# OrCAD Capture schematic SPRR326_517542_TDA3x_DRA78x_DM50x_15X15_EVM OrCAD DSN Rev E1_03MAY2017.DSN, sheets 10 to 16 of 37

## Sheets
10 SH16 - USB FTDI UART: size C; rev: A
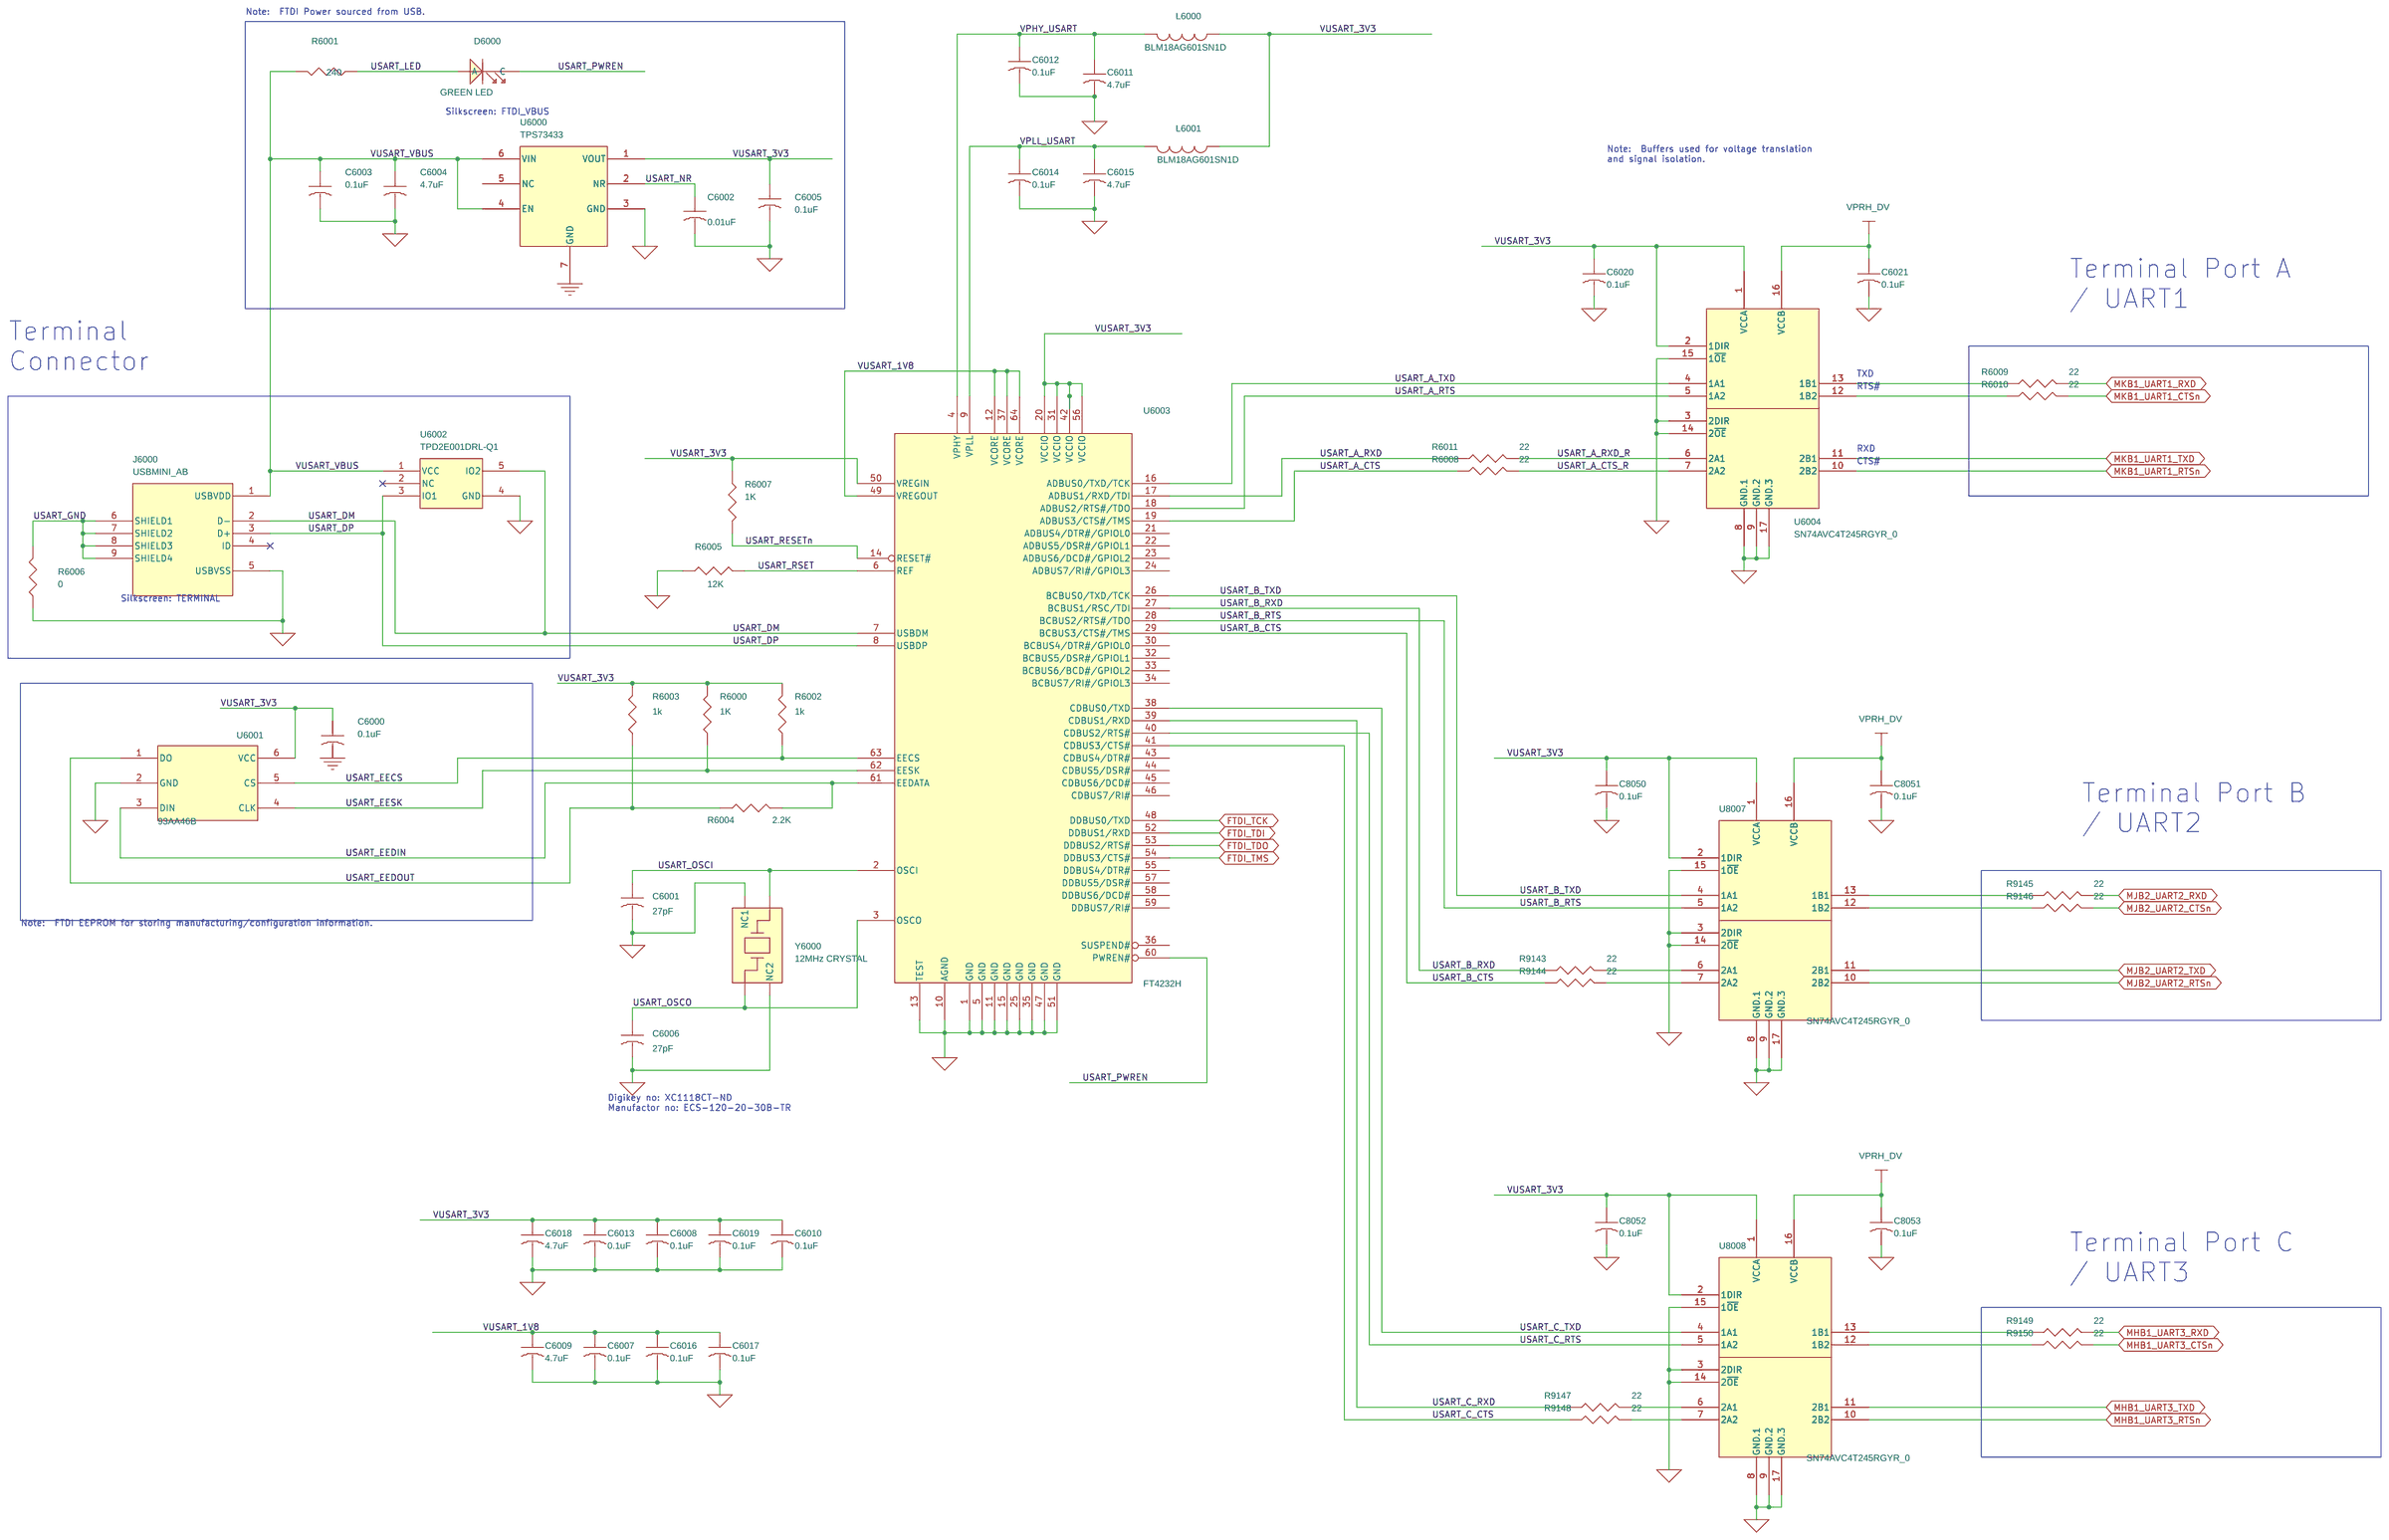
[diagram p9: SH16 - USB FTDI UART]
11 SH18 - ETHERNET: size C; rev: A
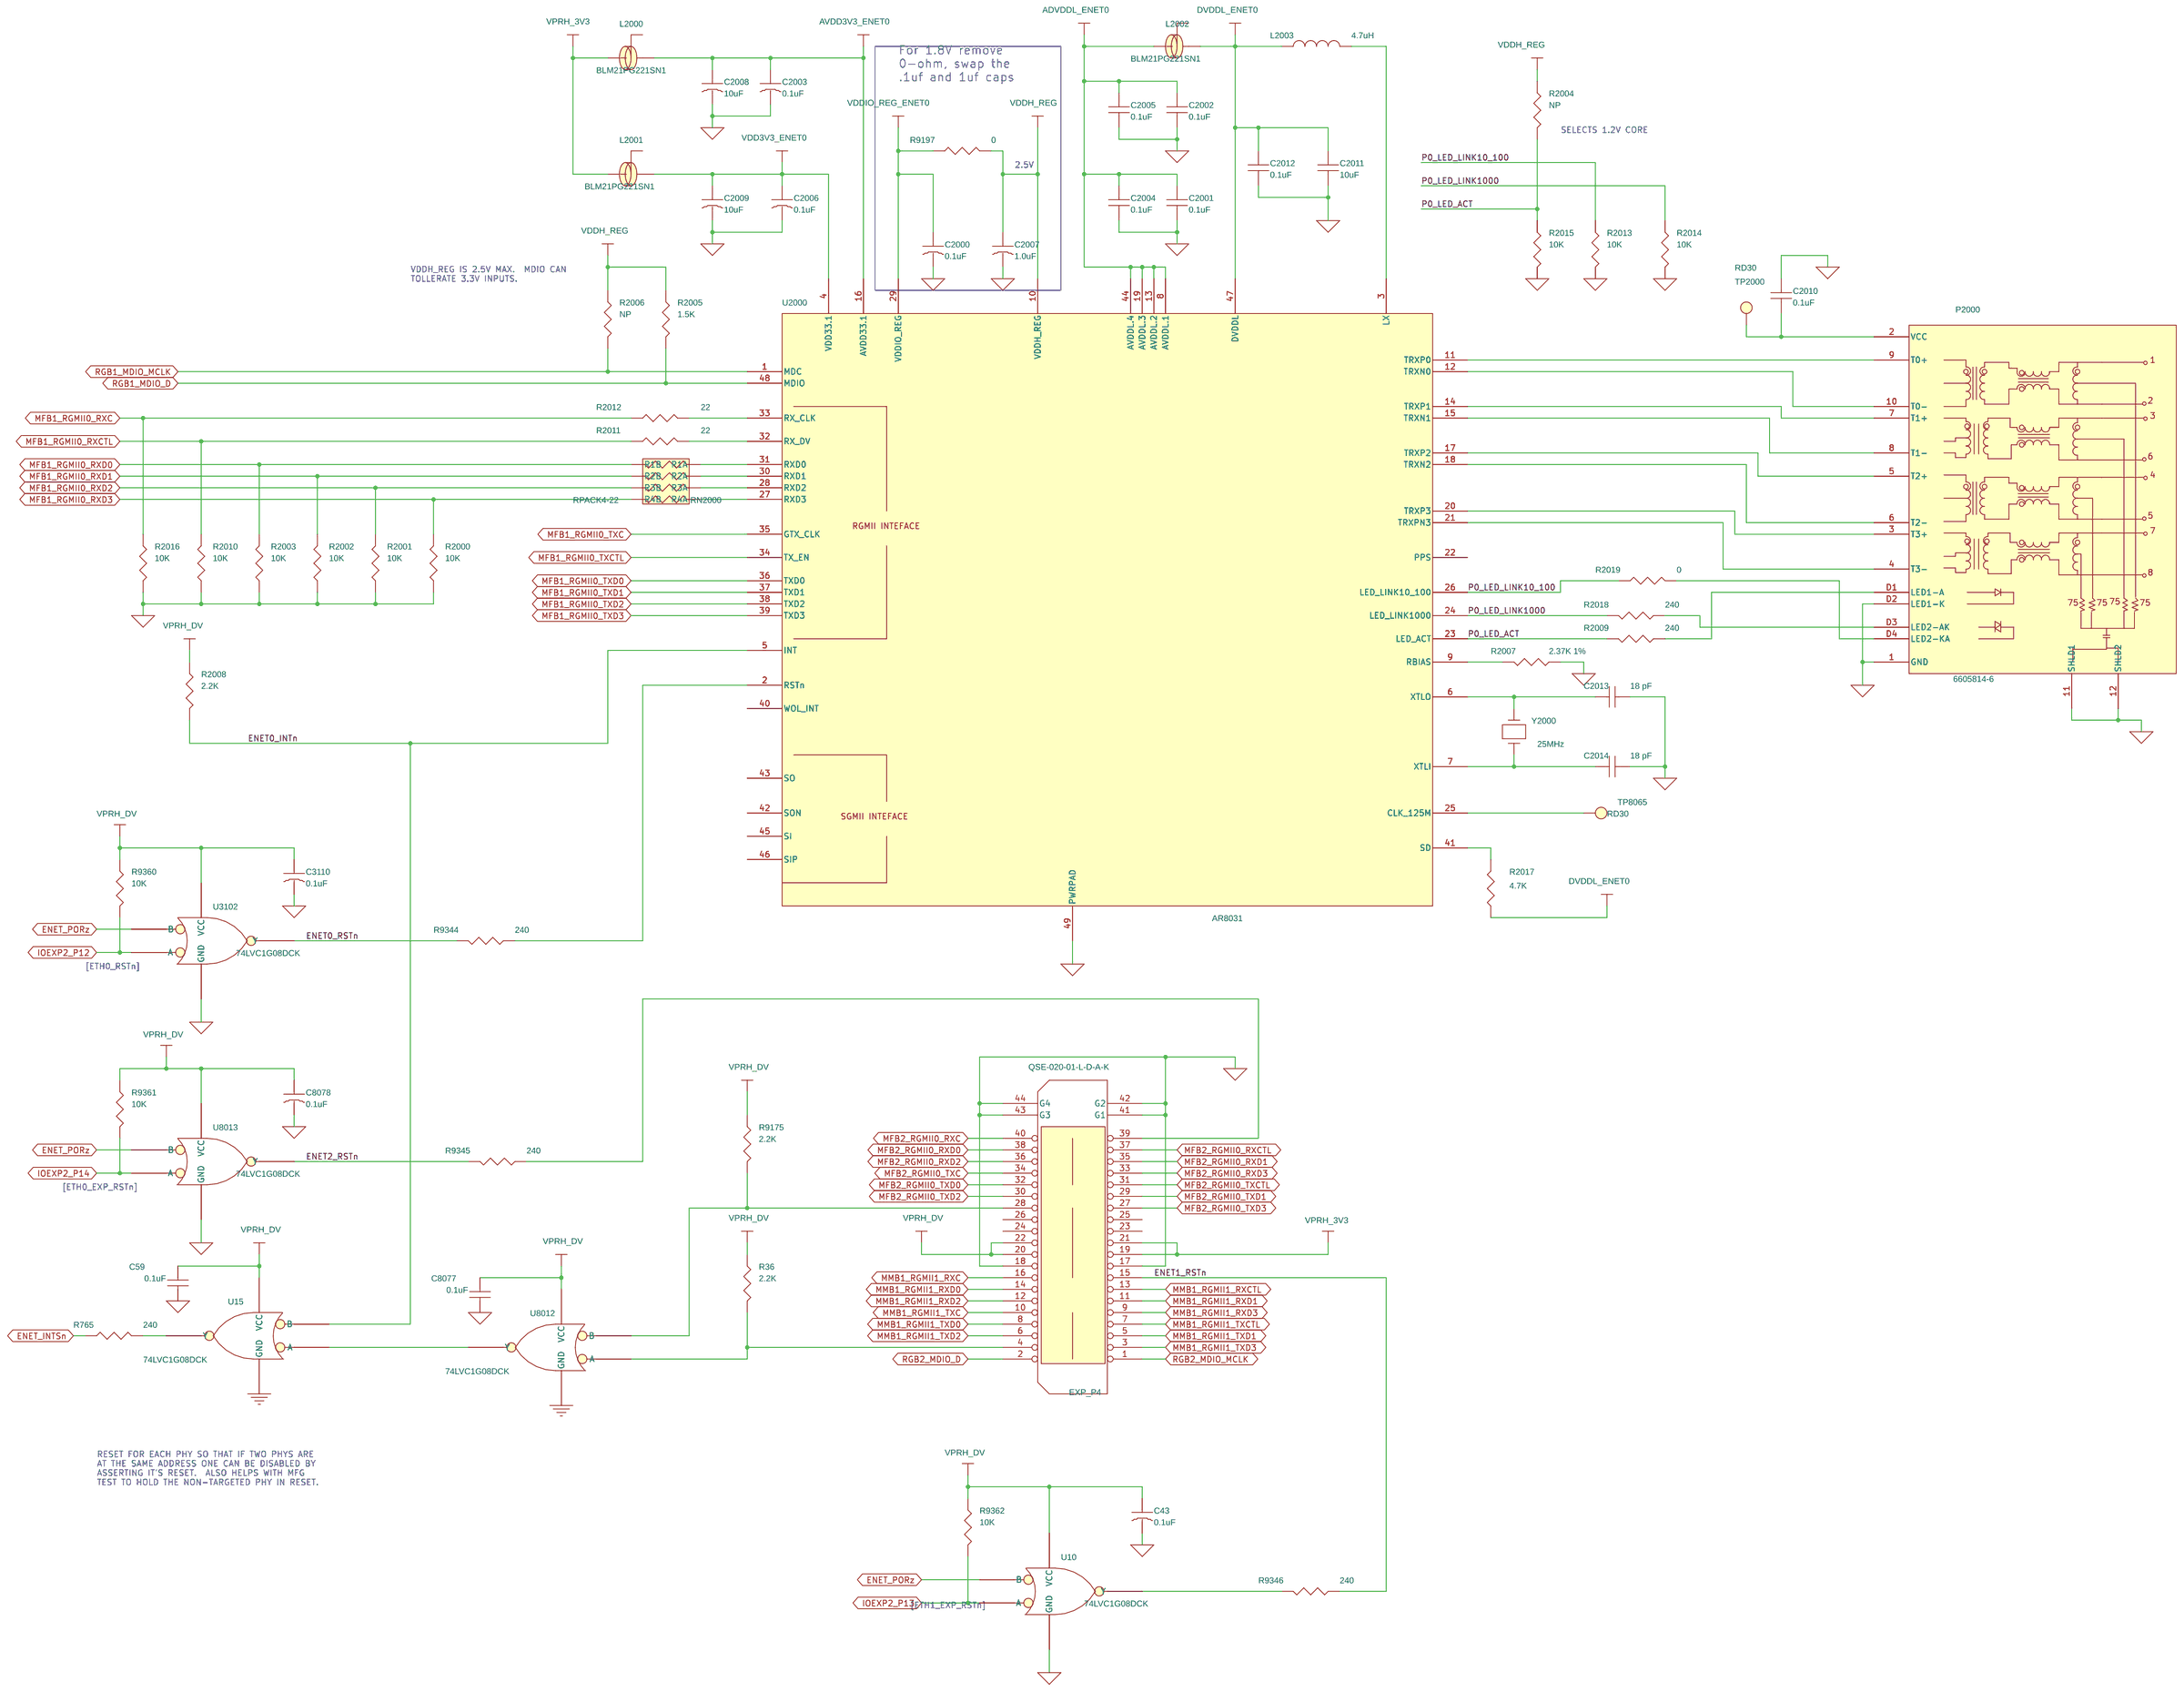
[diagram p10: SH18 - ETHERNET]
12 SH19 - POWER TPS443351DAP: size C; rev: D
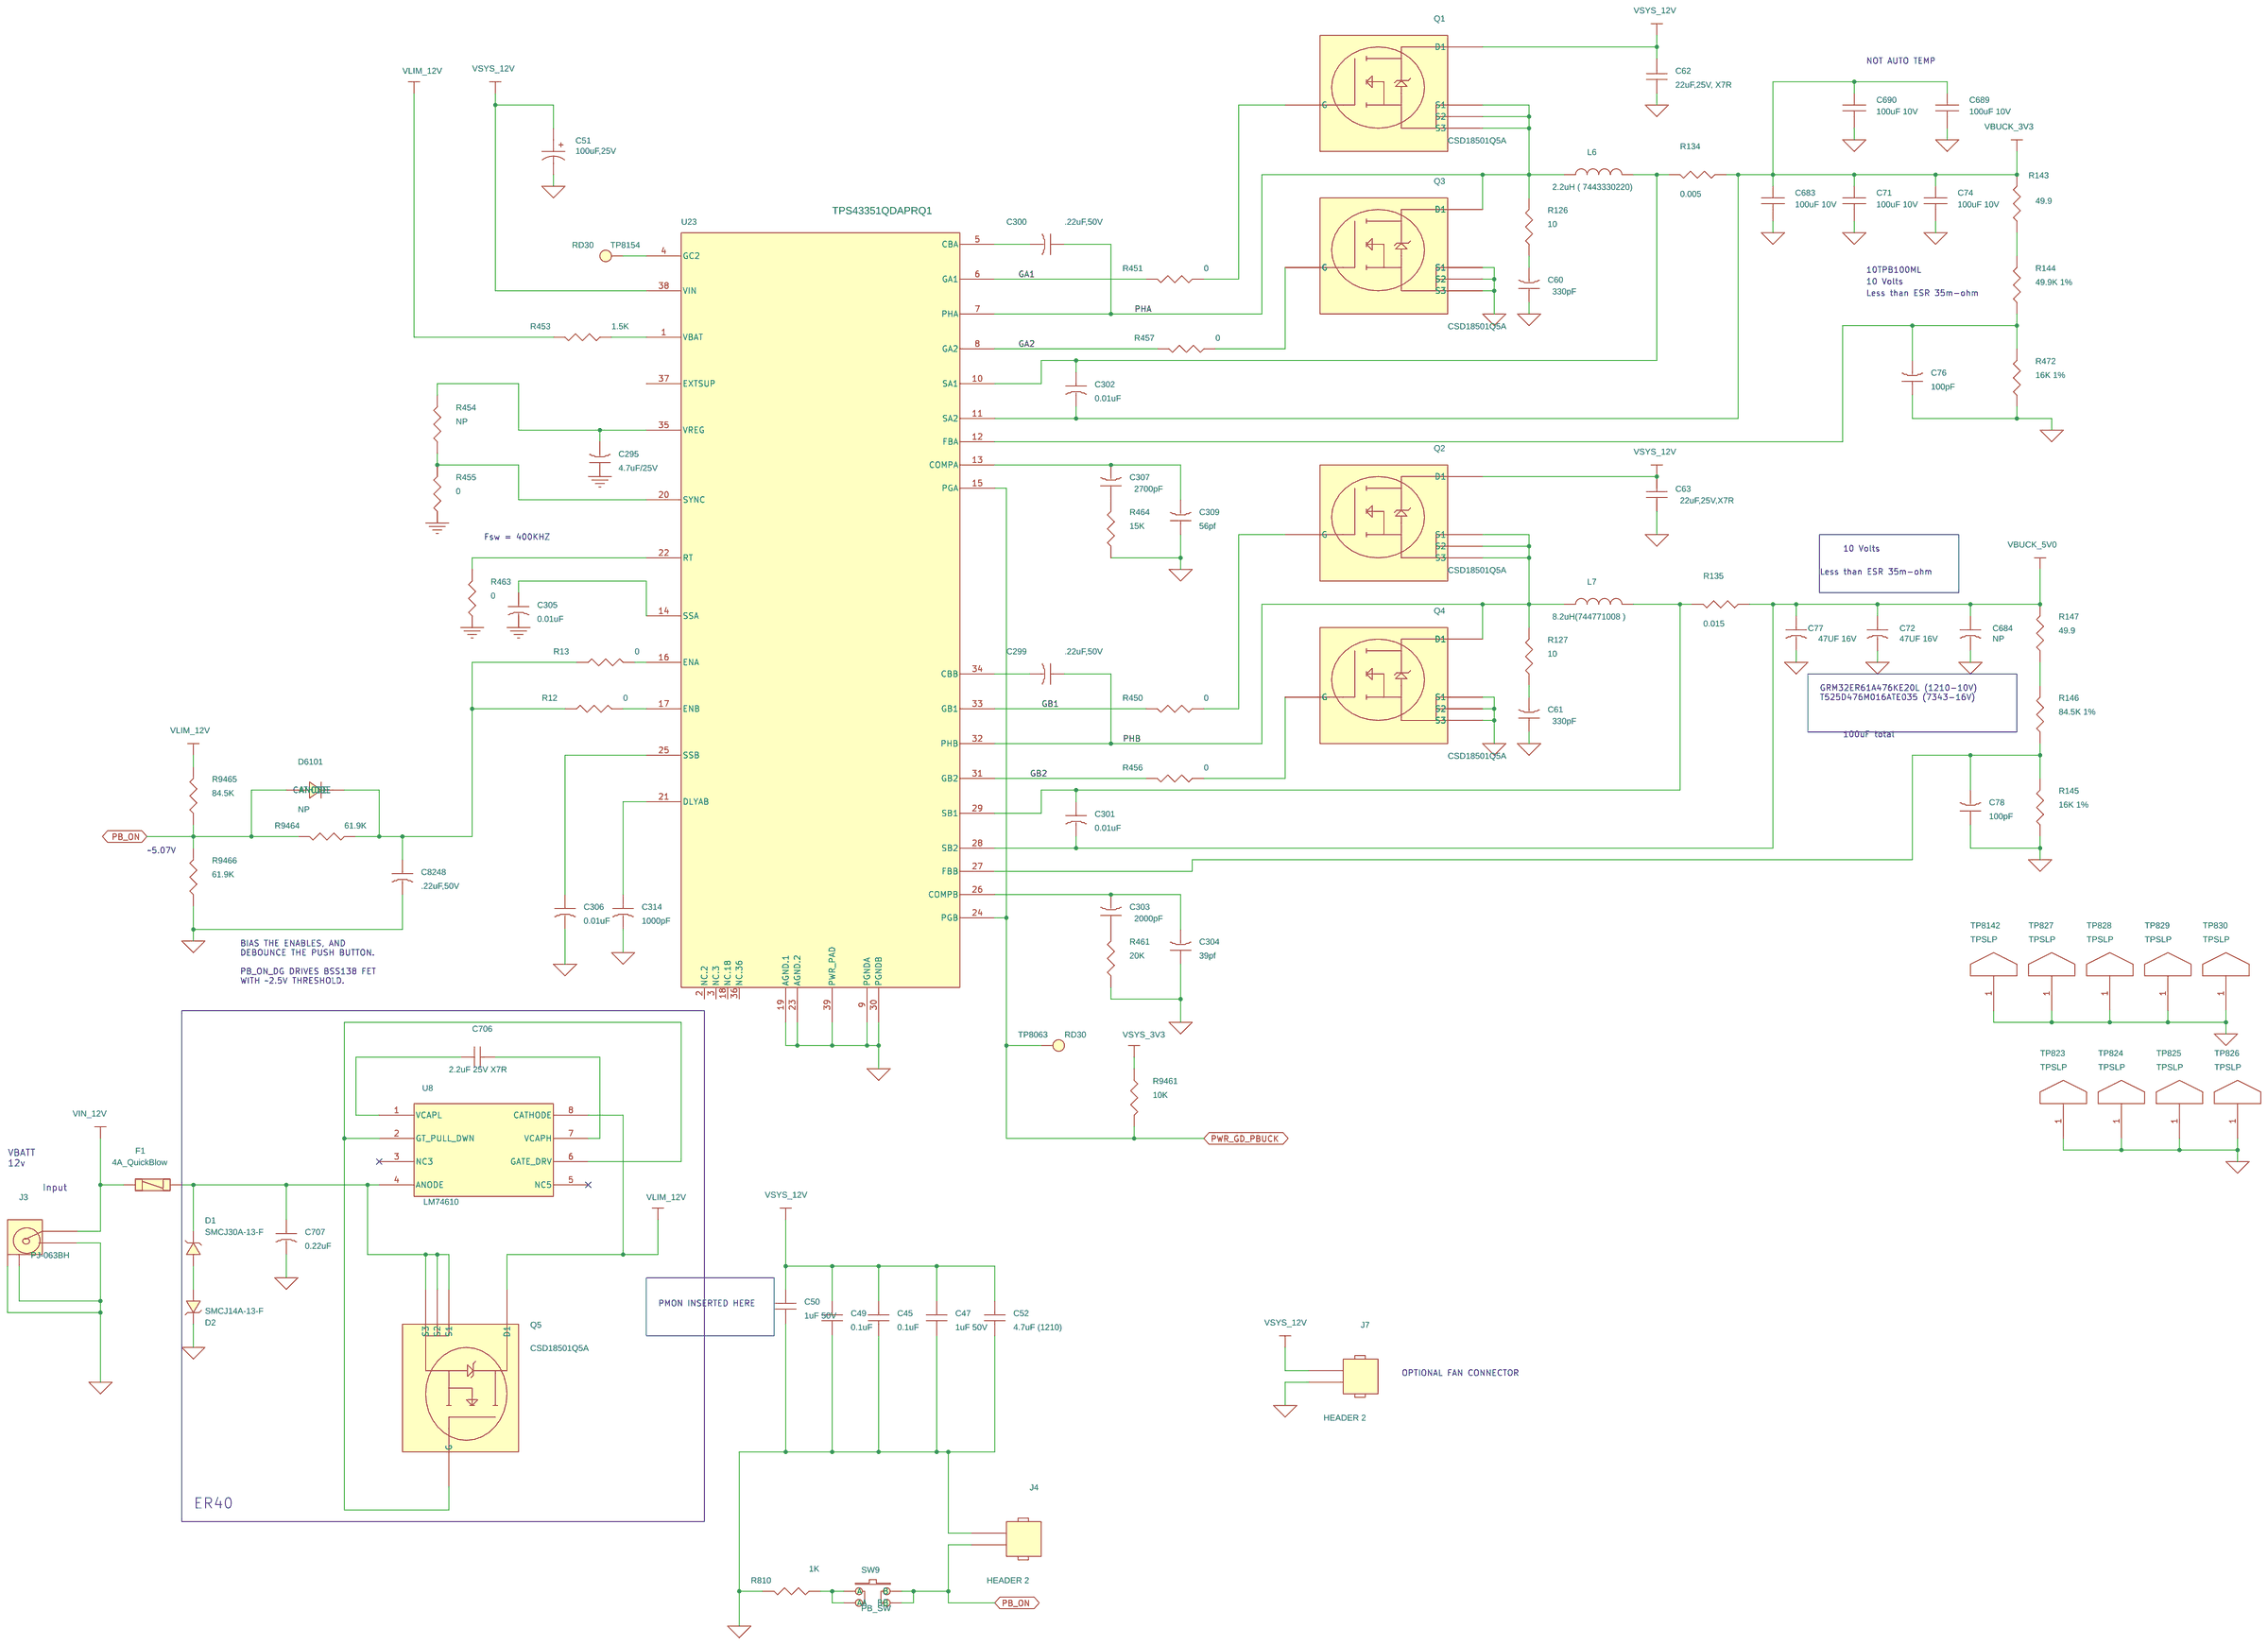
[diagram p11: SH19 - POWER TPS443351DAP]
13 SH20 - POWER PMIC: size C; rev: D
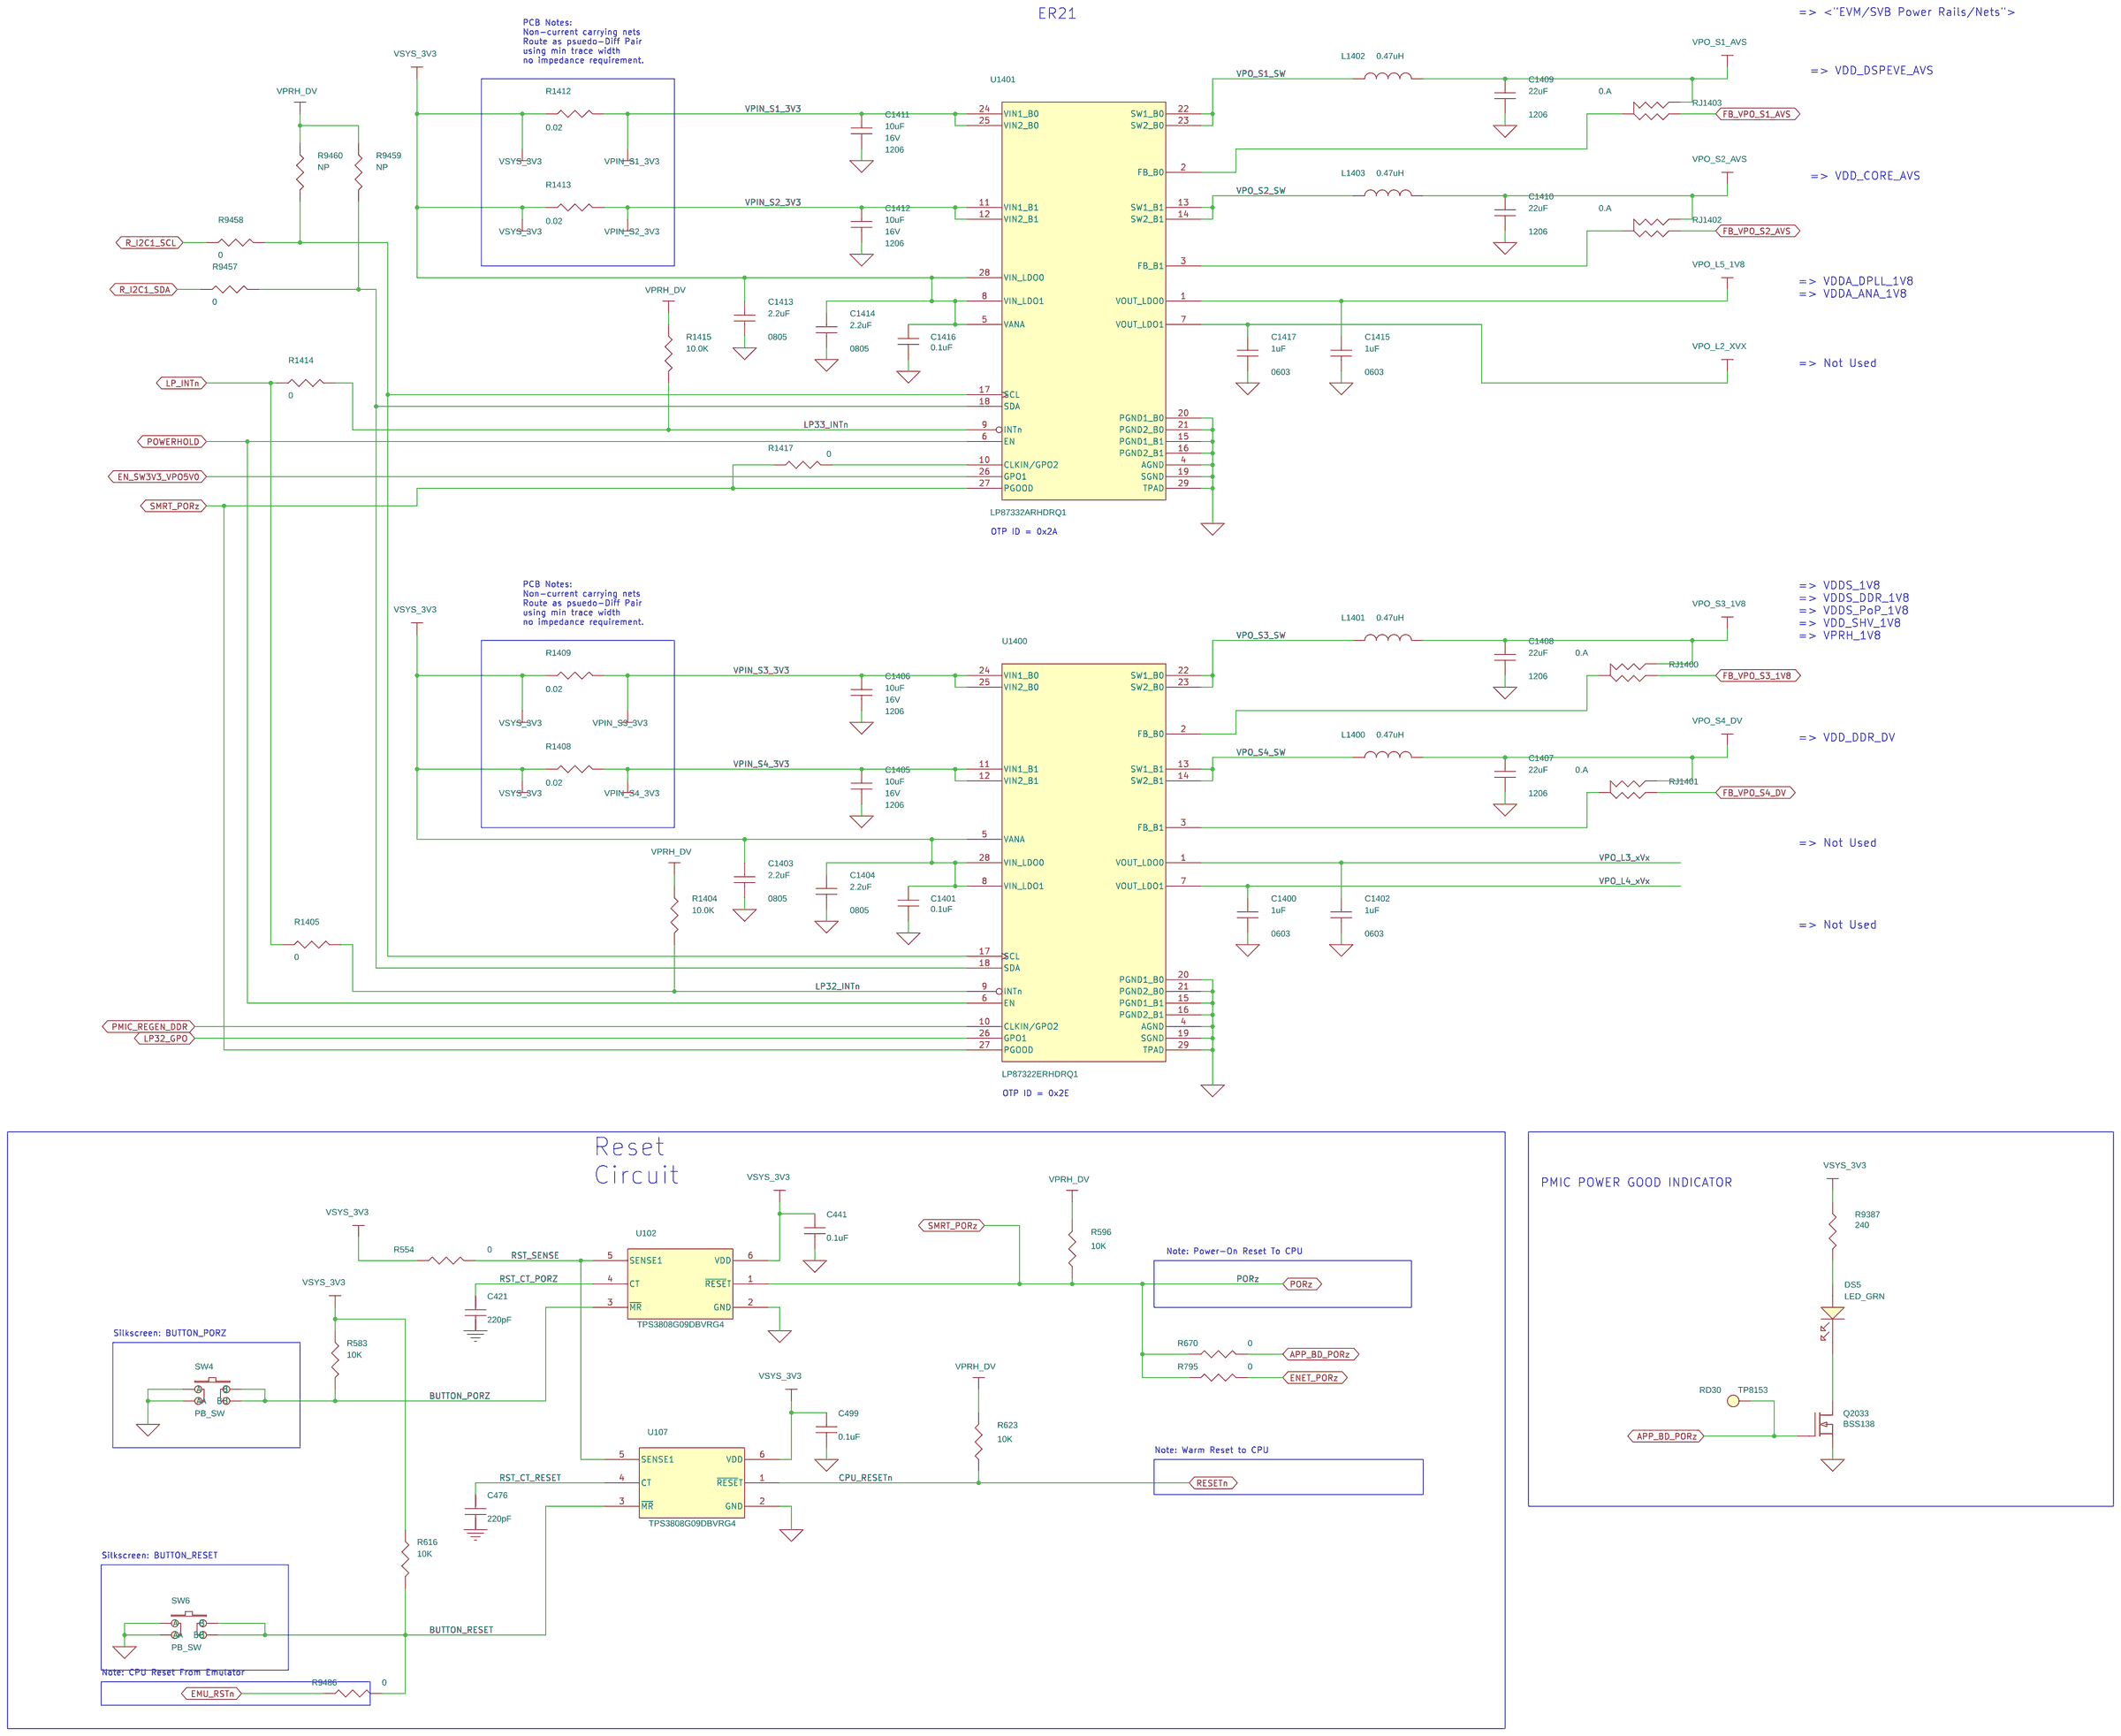
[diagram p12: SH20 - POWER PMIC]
14 SH21 - POWER MISC SWITCHES: size C; rev: E
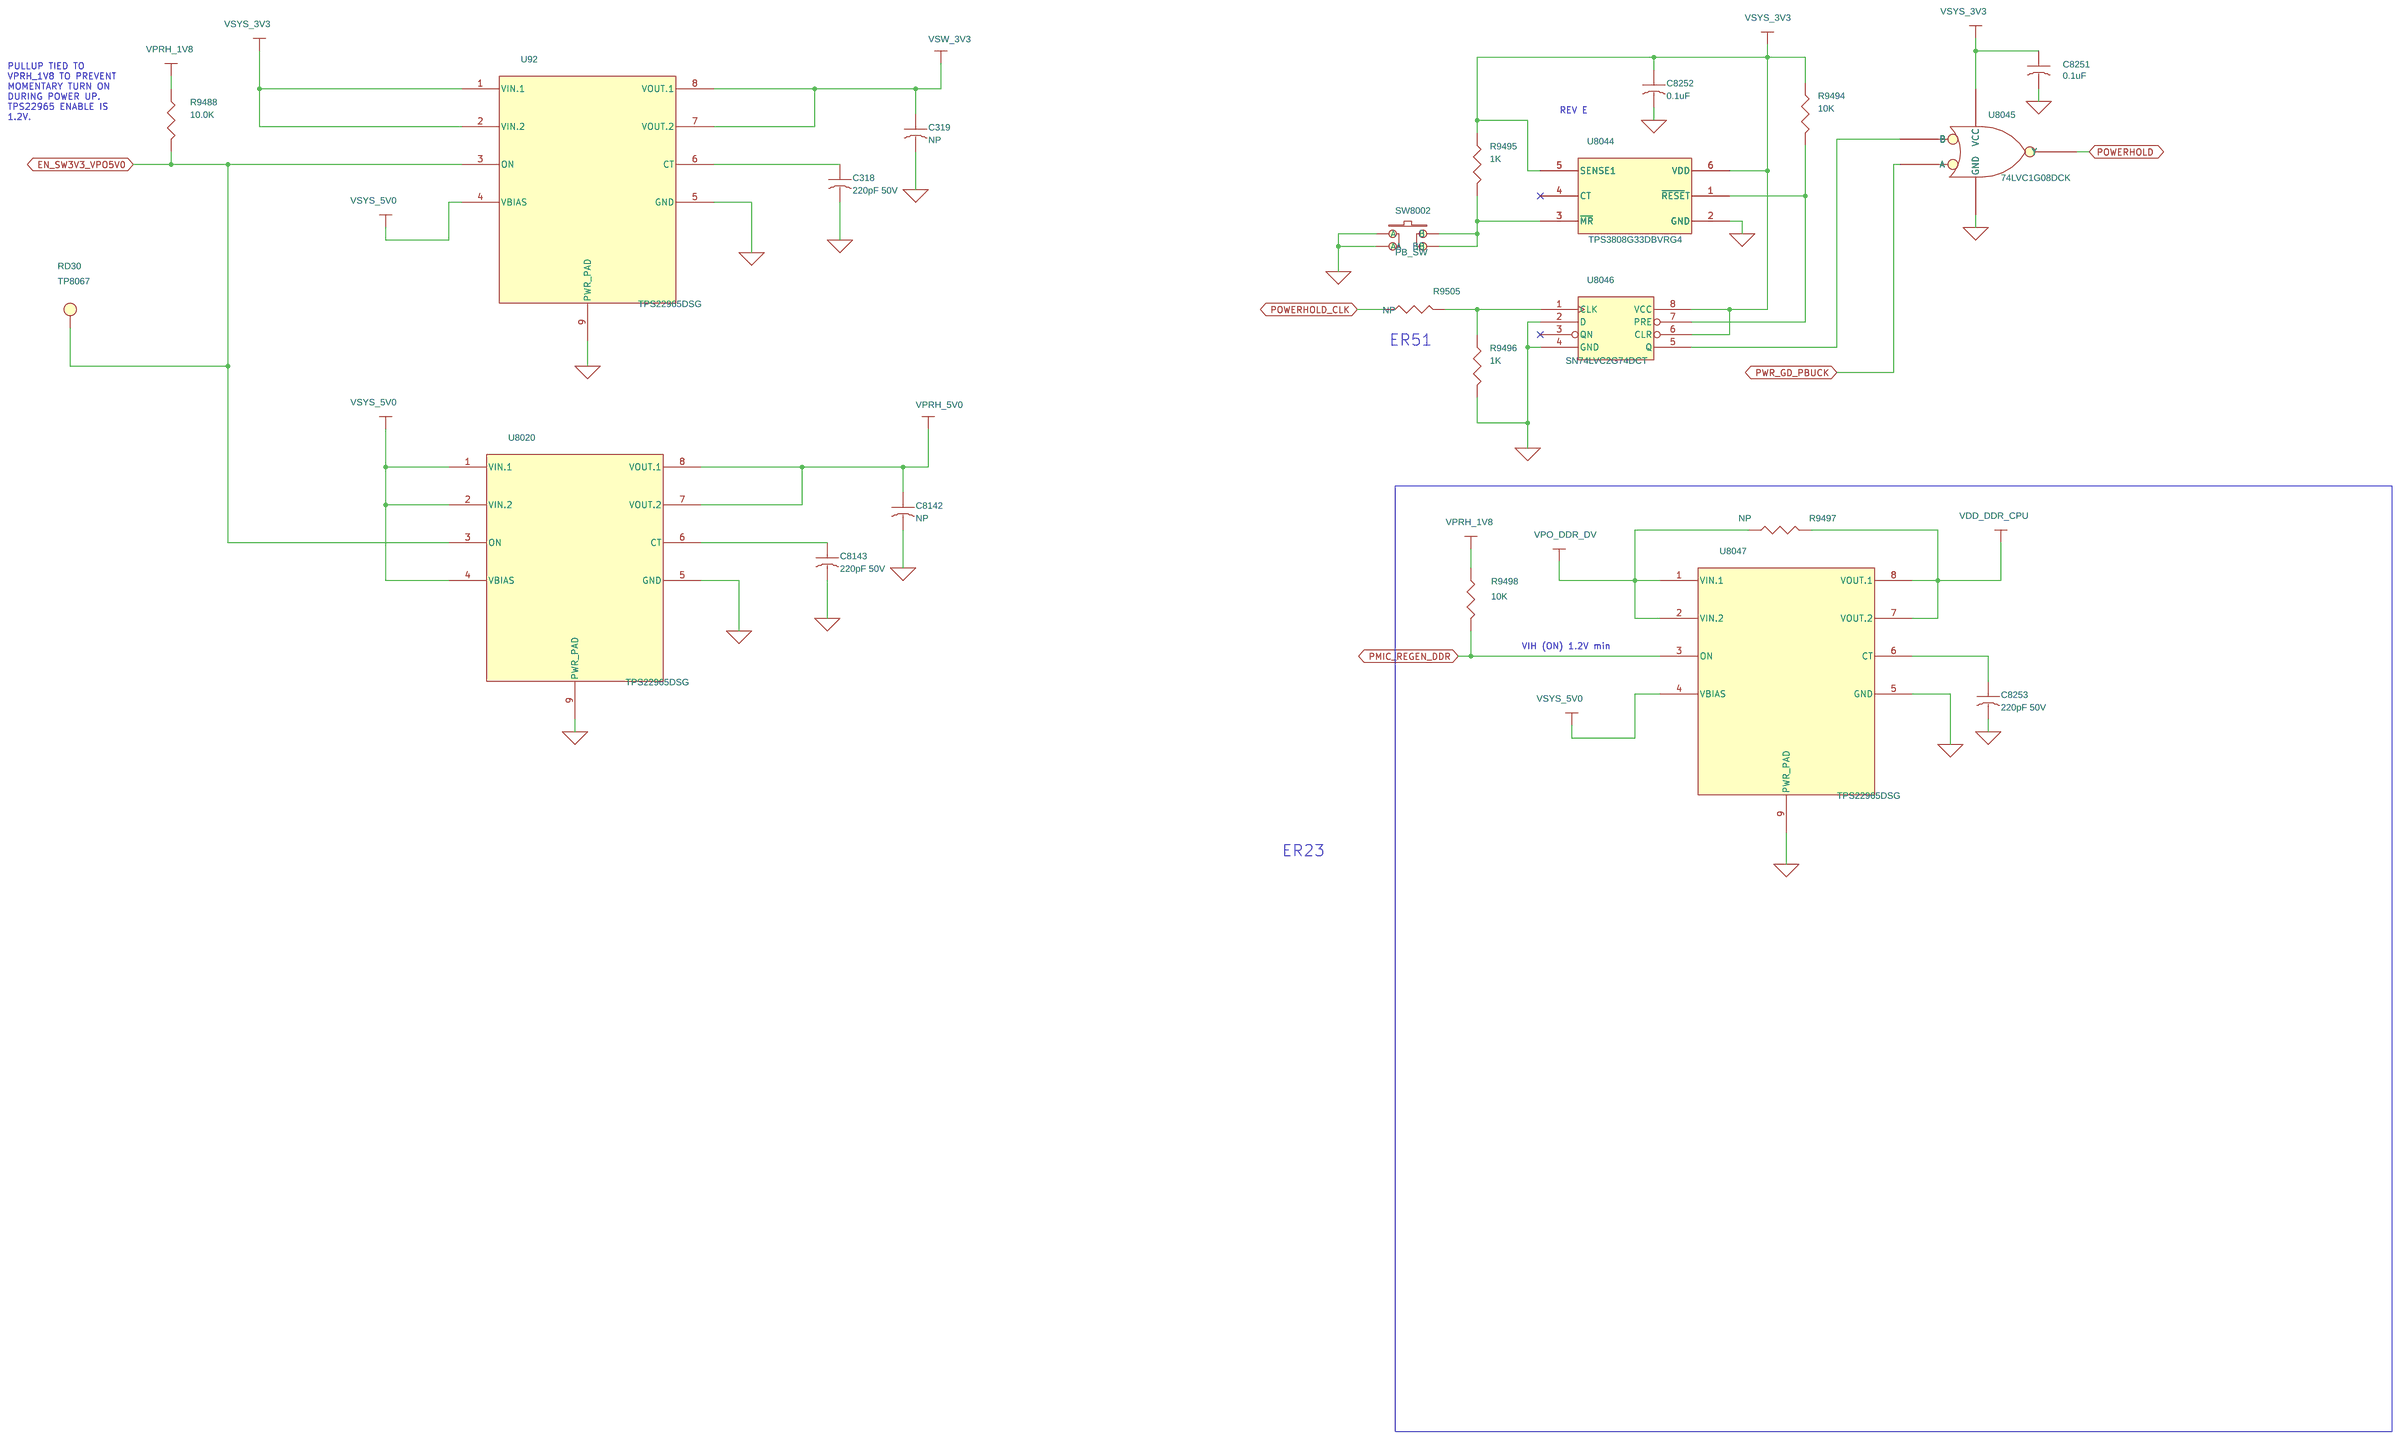
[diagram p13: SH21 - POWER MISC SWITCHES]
15 SH22 - POWER MONITORS: size C; rev: B
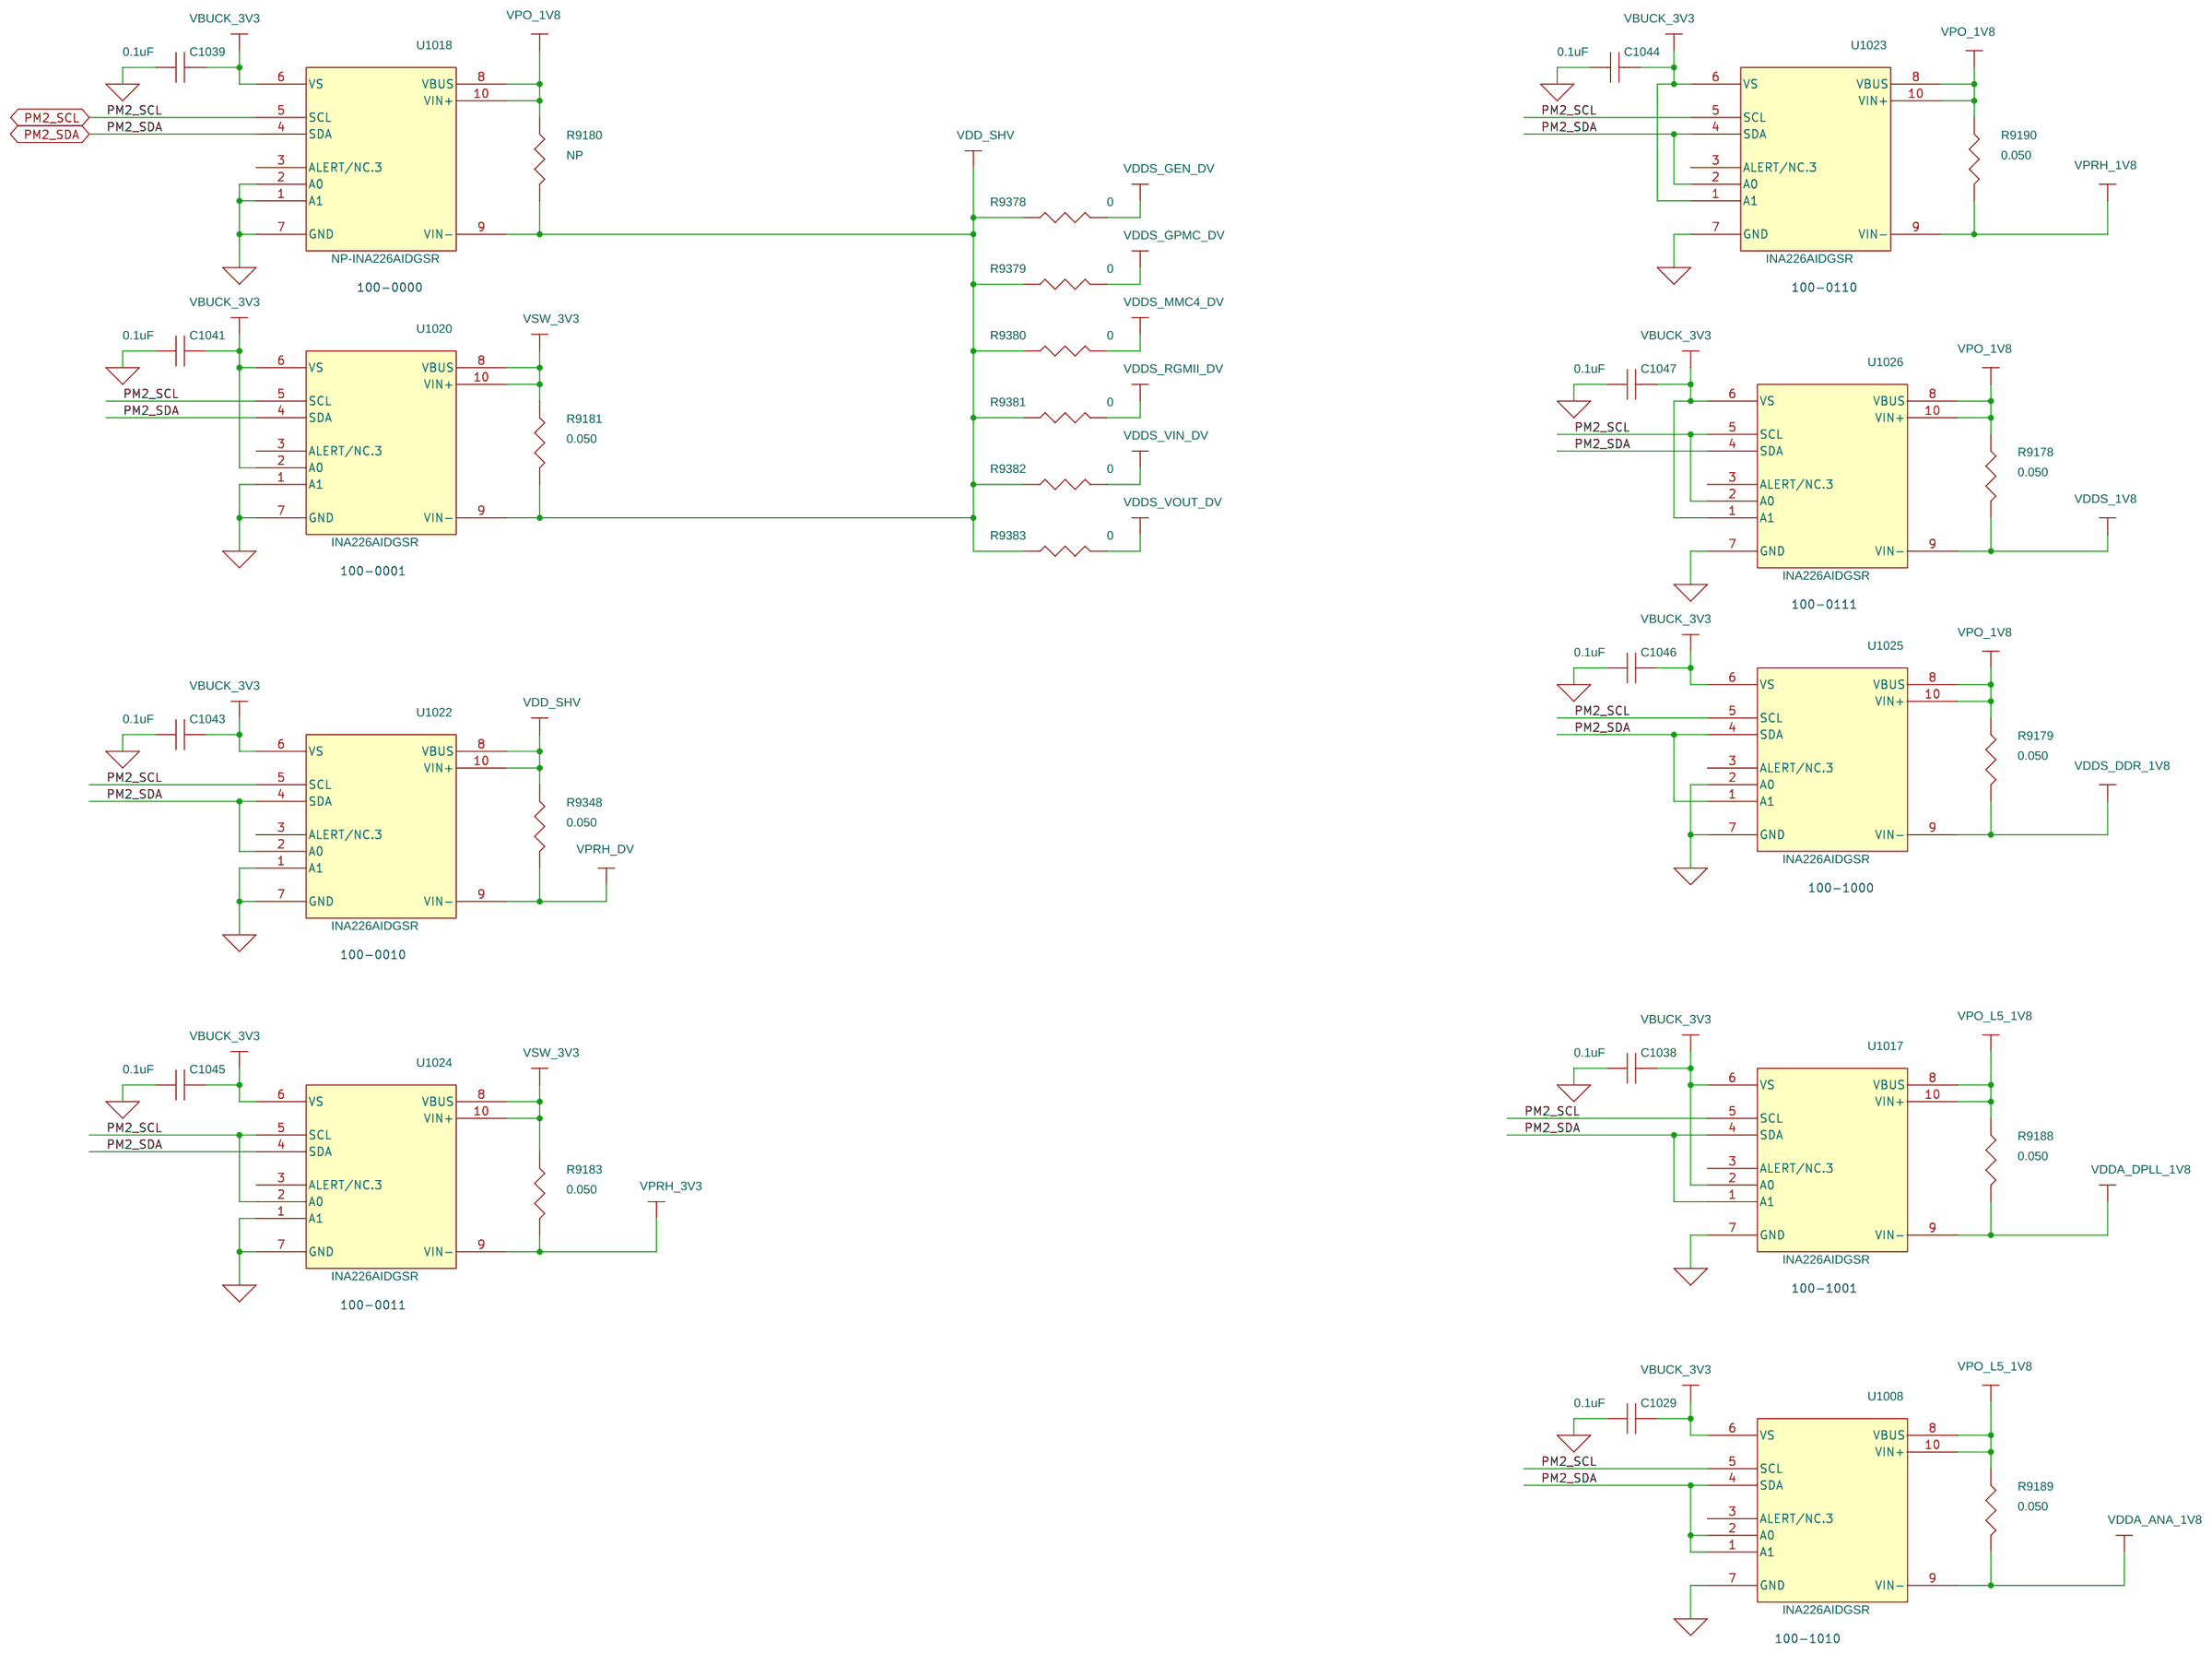
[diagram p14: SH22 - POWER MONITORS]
16 SH24 - VOUT LCD CONNECTOR: size C; rev: A
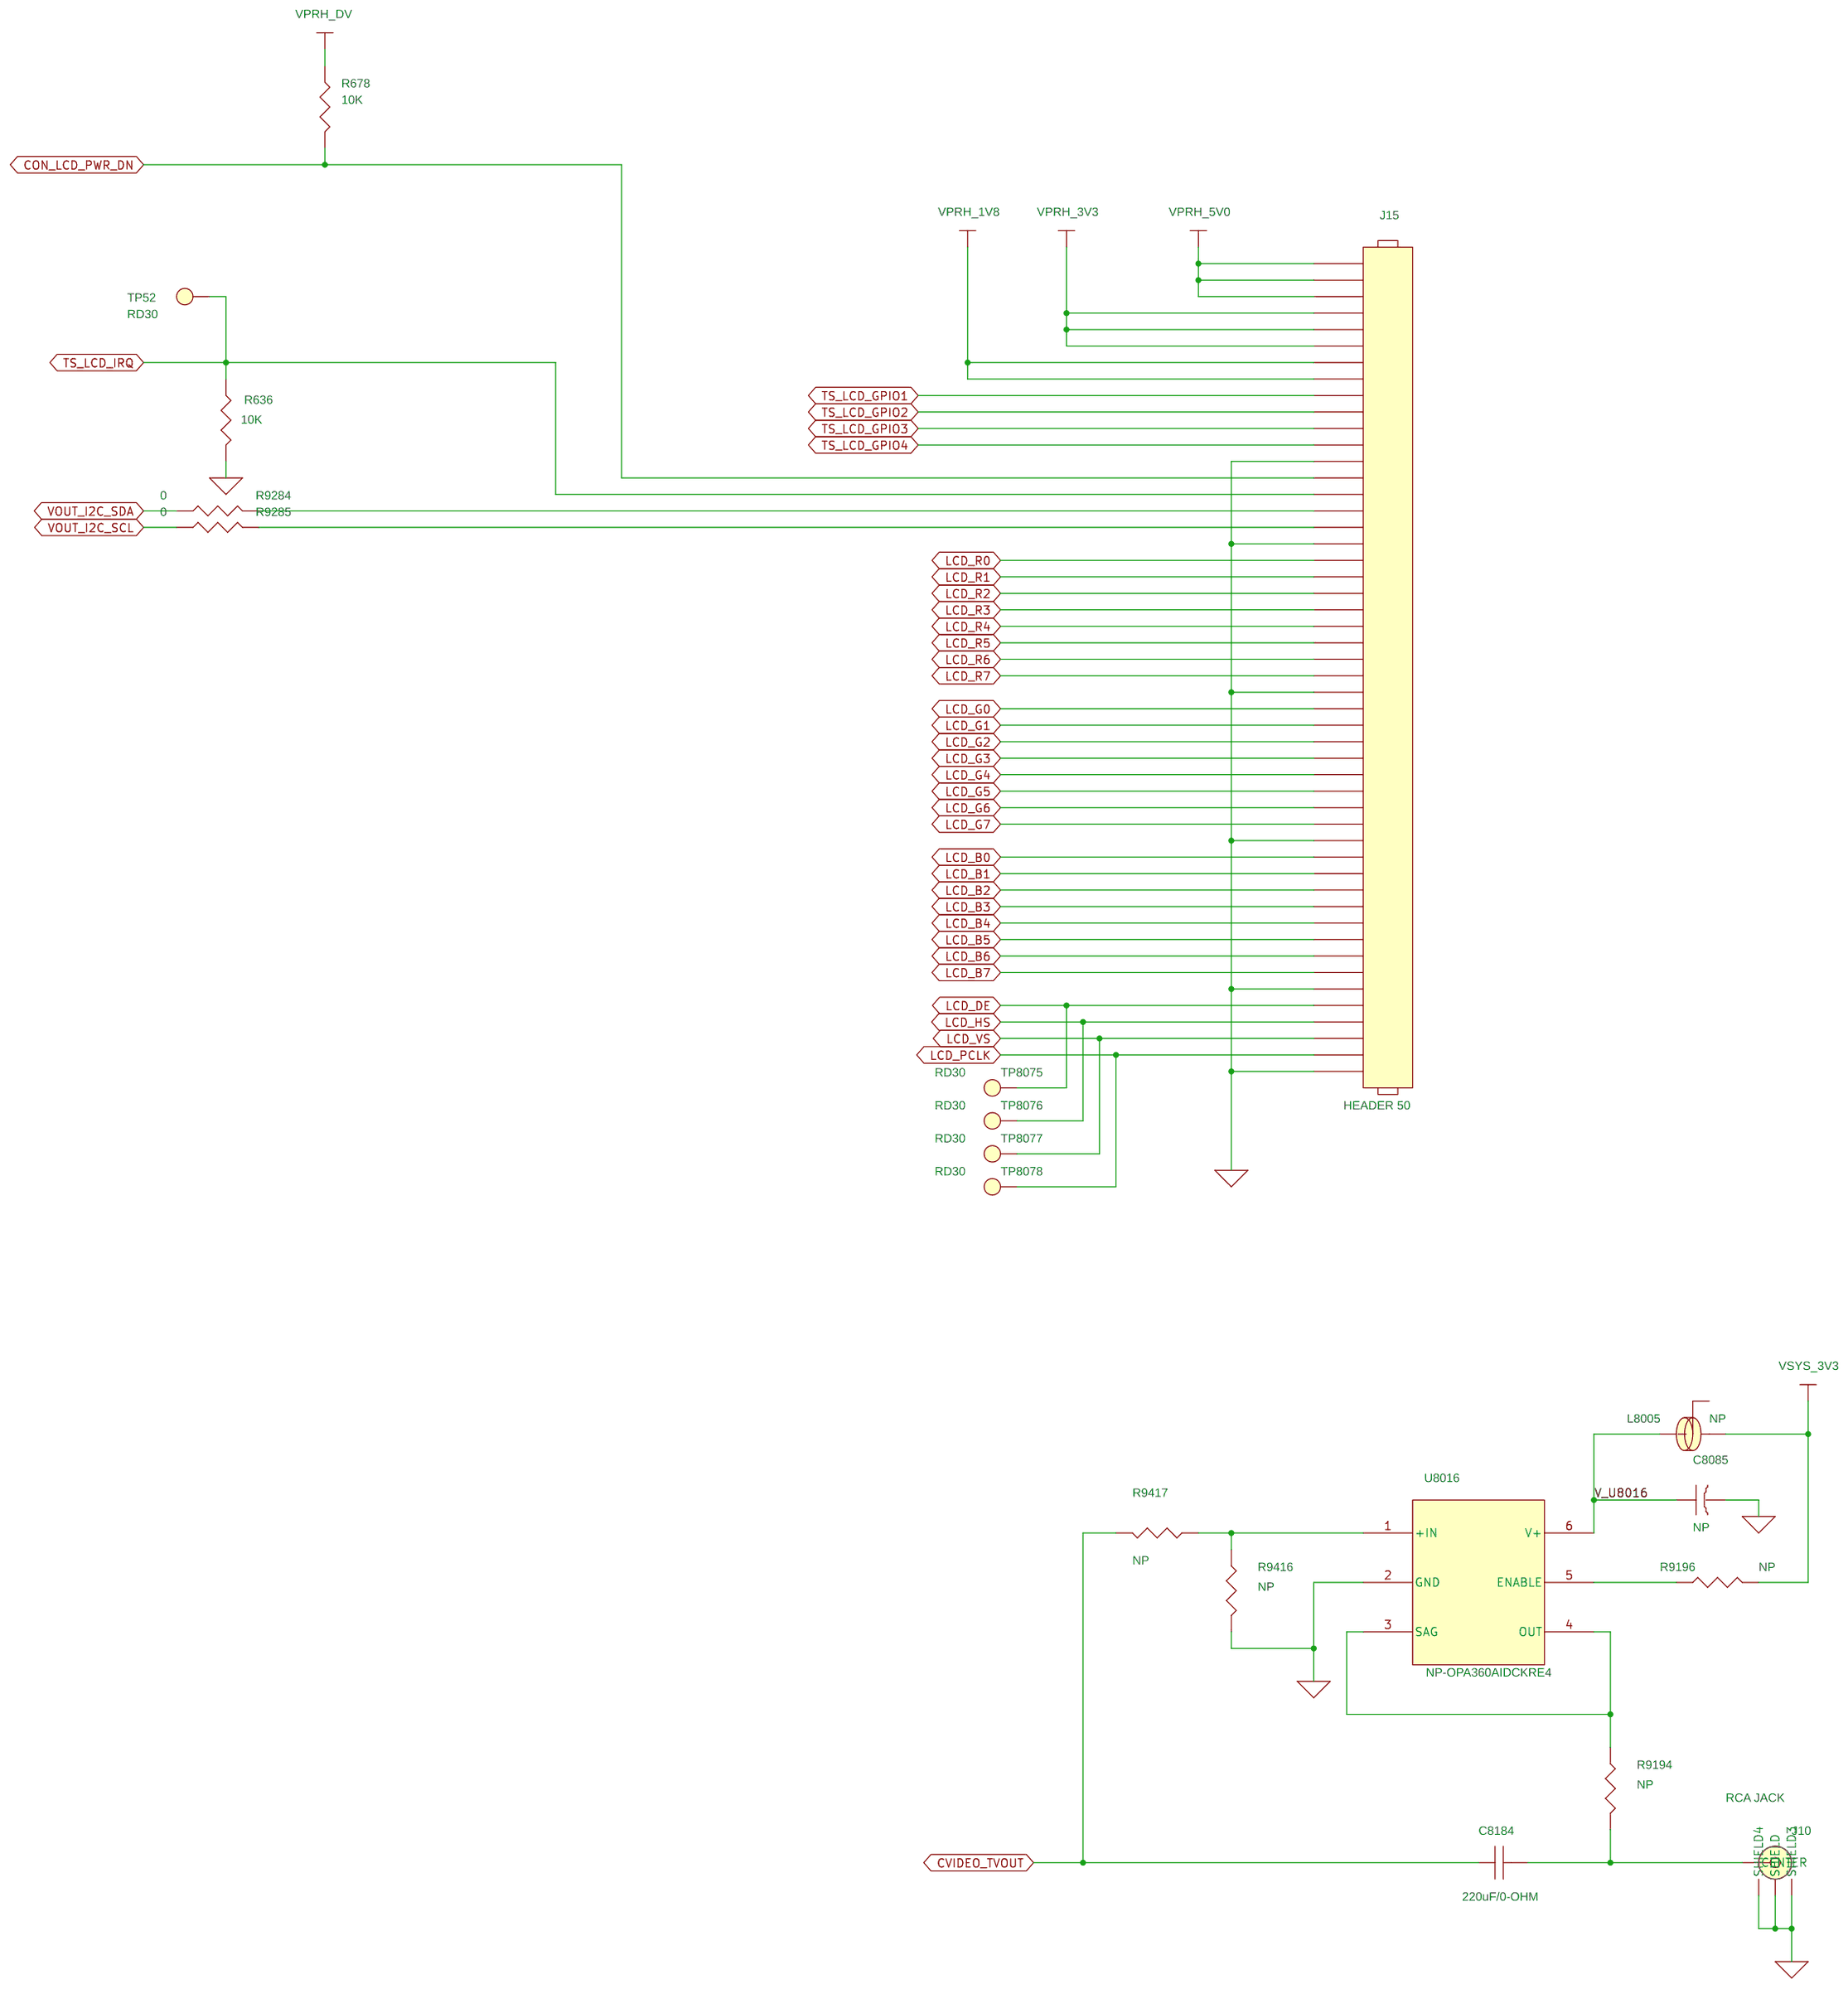
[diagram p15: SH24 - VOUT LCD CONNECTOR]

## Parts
sheet SH16 - USB FTDI UART
C6000  0.1uF  [c402-25]
C6001  27pF  [c402-25]
C6002  0.01uF  [c402-25]
C6003  0.1uF  [c402-25]
C6004  4.7uF  [C805-35X60]
C6005  0.1uF  [c402-25]
C6006  27pF  [c402-25]
C6007  0.1uF  [c402-25]
C6008  0.1uF  [c402-25]
C6009  4.7uF  [C805-35X60]
C6010  0.1uF  [c402-25]
C6011  4.7uF  [C805-35X60]
C6012  0.1uF  [c402-25]
C6013  0.1uF  [c402-25]
C6014  0.1uF  [c402-25]
C6015  4.7uF  [C805-35X60]
C6016  0.1uF  [c402-25]
C6017  0.1uF  [c402-25]
C6018  4.7uF  [C805-35X60]
C6019  0.1uF  [c402-25]
C6020  0.1uF  [c402-25]
C6021  0.1uF  [c402-25]
C8050  0.1uF  [c402-25]
C8051  0.1uF  [c402-25]
C8052  0.1uF  [c402-25]
C8053  0.1uF  [c402-25]
D6000  GREEN LED  [led603-35x45-rev]
J6000  USBMINI_AB  [SAMTEC-MUSB]
L6000  BLM18AG601SN1D  [l603-35x45]
L6001  BLM18AG601SN1D  [l603-35x45]
R6000  1K  [r402-25]
R6001  240  [r402-25]
R6002  1k  [r402-25]
R6003  1k  [r402-25]
R6004  2.2K  [r402-25]
R6005  12K  [r402-25]
R6006  0  [r402-25]
R6007  1K  [r402-25]
R6008  22  [r402-25]
R6009  22  [r402-25]
R6010  22  [r402-25]
R6011  22  [r402-25]
R9143  22  [r402-25]
R9144  22  [r402-25]
R9145  22  [r402-25]
R9146  22  [r402-25]
R9147  22  [r402-25]
R9148  22  [r402-25]
R9149  22  [r402-25]
R9150  22  [r402-25]
U6000  TPS73433  [drv6-12x30]
U6001  93AA46B  [DBV6-27X39-6]
U6002  TPD2E001DRL-Q1  [drl5-12x40]
U6003  FT4232H  [PQFP64PM]
U6004  SN74AVC4T245RGYR_0  [rgy16-12x34]
U8007  SN74AVC4T245RGYR_0  [rgy16-12x34]
U8008  SN74AVC4T245RGYR_0  [rgy16-12x34]
Y6000  12MHz CRYSTAL  [xtal4-63x50-ecx53b]
sheet SH18 - ETHERNET
C43  0.1uF  [c402-25]
C59  0.1uF  [c402-25]
C2000  0.1uF  [c603-35x45]
C2001  0.1uF  [c402-25]
C2002  0.1uF  [c402-25]
C2003  0.1uF  [c402-25]
C2004  0.1uF  [c402-25]
C2005  0.1uF  [c402-25]
C2006  0.1uF  [c402-25]
C2007  1.0uF  [c603-35x45]
C2008  10uF  [c805-35x60]
C2009  10uF  [c805-35x60]
C2010  0.1uF  [c402-25]
C2011  10uF  [c805-35x60]
C2012  0.1uF  [c402-25]
C2013  18 pF  [c402-25]
C2014  18 pF  [c402-25]
C3110  0.1uF  [c402-25]
C8077  0.1uF  [c402-25]
C8078  0.1uF  [c402-25]
EXP_P4  QSE-020-01-L-D-A-K  [QSE_020]
L2000  BLM21PG221SN1  [l805-35x60]
L2001  BLM21PG221SN1  [l805-35x60]
L2002  BLM21PG221SN1  [l805-35x60]
L2003  4.7uH  [ind2-mipf2016]
P2000  6605814-6  [amp-6605814]
R36  2.2K  [r402-25]
R765  240  [r402-25]
R2000  10K  [r402-25]
R2001  10K  [r402-25]
R2002  10K  [r402-25]
R2003  10K  [r402-25]
R2004  NP  [r402-25]
R2005  1.5K  [r402-25]
R2006  NP  [r402-25]
R2007  2.37K 1%  [r402-25]
R2008  2.2K  [r402-25]
R2009  240  [r402-25]
R2010  10K  [r402-25]
R2011  22  [r402-25]
R2012  22  [r402-25]
R2013  10K  [r402-25]
R2014  10K  [r402-25]
R2015  10K  [r402-25]
R2016  10K  [r402-25]
R2017  4.7K  [r402-25]
R2018  240  [r402-25]
R2019  0  [r402-25]
R9175  2.2K  [r402-25]
R9197  0  [r402-25]
R9344  240  [r402-25]
R9345  240  [r402-25]
R9346  240  [r402-25]
R9360  10K  [r402-25]
R9361  10K  [r402-25]
R9362  10K  [r402-25]
RN2000  RPACK4-22  [rpak8-10x25-28v]
TP2000  RD30  [tp-30RD13]
TP8065  RD30  [tp-30RD13]
U10  74LVC1G08DCK  [dck-5]
U15  74LVC1G08DCK  [dck-5]
U2000  AR8031  [qfn48-6mmsq]
U3102  74LVC1G08DCK  [dck-5]
U8012  74LVC1G08DCK  [dck-5]
U8013  74LVC1G08DCK  [dck-5]
Y2000  25MHz  [xtal2-75x94]
sheet SH19 - POWER TPS443351DAP
C45  0.1uF  [c603-35x45]
C47  1uF 50V  [c805-35x60]
C49  0.1uF  [c603-35x45]
C50  1uF 50V  [c805-35x60]
C51  100uF,25V  [c7343-84x118]
C52  4.7uF (1210)  [c1210-70x102]
C60  330pF  [c603-35x45]
C61  330pF  [c603-35x45]
C62  22uF,25V, X7R  [c1210-70x102]
C63  22uF,25V,X7R  [c1210-70x102]
C71  100uF 10V  [c7343-84x118]
C72  47UF 16V  [c1210-c7343-dual]
C74  100uF 10V  [c7343-84x118]
C76  100pF  [c603-35x45]
C77  47UF 16V  [c1210-c7343-dual]
C78  100pF  [c603-35x45]
C295  4.7uF/25V  [c805-35x60]
C299  .22uF,50V  [c603-35x45]
C300  .22uF,50V  [c603-35x45]
C301  0.01uF  [c402-25]
C302  0.01uF  [c402-25]
C303  2000pF  [c402-25]
C304  39pf  [c402-25]
C305  0.01uF  [c402-25]
C306  0.01uF  [c402-25]
C307  2700pF  [c402-25]
C309  56pf  [c402-25]
C314  1000pF  [c402-25]
C683  100uF 10V  [c7343-84x118]
C684  NP  [c1210-70x102]
C689  100uF 10V  [c7343-84x118]
C690  100uF 10V  [c7343-84x118]
C706  2.2uF 25V X7R  [c805-35x60]
C707  0.22uF  [c603-35x45]
C8248  .22uF,50V  [c603-35x45]
D1  SMCJ30A-13-F  [SMC-80X128]
D2  SMCJ14A-13-F  [SMC-80X128]
D6101  NP  [sod123-36x48]
F1  4A_QuickBlow  [FUSEFOLDER-OMNI-BLOK]
J3  PJ-063BH  [pwrjack-cui-pj063bh]
J4  HEADER 2  [JUMP1X2-6040]
J7  HEADER 2  [JUMP1X2-6040]
L6  2.2uH ( 7443330220)  [choke-power-we-hcc]
L7  8.2uH(744771008 )  [ind2-115x213-12mm]
Q1  CSD18501Q5A  [pwr-q5a-slps319]
Q2  CSD18501Q5A  [pwr-q5a-slps319]
Q3  CSD18501Q5A  [pwr-q5a-slps319]
Q4  CSD18501Q5A  [pwr-q5a-slps319]
Q5  CSD18501Q5A  [pwr-q5a-slps319]
R12  0  [r402-25]
R13  0  [r402-25]
R126  10  [r603-35X45]
R127  10  [r603-35X45]
R134  0.005  [r2725-125x250]
R135  0.015  [R2512]
R143  49.9  [r402-25]
R144  49.9K 1%  [r603-35x45]
R145  16K 1%  [r603-35x45]
R146  84.5K 1%  [r603-35x45]
R147  49.9  [r402-25]
R450  0  [r402-25]
R451  0  [r402-25]
R453  1.5K  [r402-25]
R454  NP  [r402-25]
R455  0  [r402-25]
R456  0  [r402-25]
R457  0  [r402-25]
R461  20K  [r402-25]
R463  0  [r402-25]
R464  15K  [r402-25]
R472  16K 1%  [r603-35x45]
R810  1K  [r402-25]
R9461  10K  [r402-25]
R9464  61.9K  [r603-35X45]
R9465  84.5K  [r603-35X45]
R9466  61.9K  [r603-35X45]
SW9  PB_SW  [SW4-7914G]
TP823  TPSLP  [TP1-70X135]
TP824  TPSLP  [TP1-70X135]
TP825  TPSLP  [TP1-70X135]
TP826  TPSLP  [TP1-70X135]
TP827  TPSLP  [TP1-70X135]
TP828  TPSLP  [TP1-70X135]
TP829  TPSLP  [TP1-70X135]
TP830  TPSLP  [TP1-70X135]
TP8063  RD30  [tp-30RD13]
TP8142  TPSLP  [TP1-70X135]
TP8154  RD30  [tp-30RD13]
U8  LM74610  [dgk8-14x70]
U23  TPS43351QDAPRQ1  [dap38]
sheet SH20 - POWER PMIC
C421  220pF  [c402-25]
C441  0.1uF  [c402-25]
C476  220pF  [c402-25]
C499  0.1uF  [c402-25]
C1400  1uF  [c603-35x45]
C1401  0.1uF  [c402-25rd]
C1402  1uF  [c603-35x45]
C1403  2.2uF  [c805-35x60]
C1404  2.2uF  [c805-35x60]
C1405  10uF  [c1206-40x70]
C1406  10uF  [c1206-40x70]
C1407  22uF  [c1206-40x70]
C1408  22uF  [c1206-40x70]
C1409  22uF  [c1206-40x70]
C1410  22uF  [c1206-40x70]
C1411  10uF  [c1206-40x70]
C1412  10uF  [c1206-40x70]
C1413  2.2uF  [c805-35x60]
C1414  2.2uF  [c805-35x60]
C1415  1uF  [c603-35x45]
C1416  0.1uF  [c402-25rd]
C1417  1uF  [c603-35x45]
DS5  LED_GRN  [led1206-59x59]
L1400  0.47uH  [ind2520-40x80]
L1401  0.47uH  [ind2520-40x80]
L1402  0.47uH  [ind2520-40x80]
L1403  0.47uH  [ind2520-40x80]
Q2033  BSS138  [SOT23-28X44-GSD]
R554  0  [r402-25]
R583  10K  [r402-25]
R596  10K  [r402-25]
R616  10K  [r402-25]
R623  10K  [r402-25]
R670  0  [r201-6p6spc]
R795  0  [r402-25]
R1404  10.0K  [r402-25]
R1405  0  [r402-25]
R1408  0.02  [r603-35x45]
R1409  0.02  [r603-35x45]
R1412  0.02  [r603-35x45]
R1413  0.02  [r603-35x45]
R1414  0  [r402-25]
R1415  10.0K  [r402-25]
R1417  0  [r402-25]
R9387  240  [r402-25]
R9457  0  [r402-25]
R9458  0  [r402-25]
R9459  NP  [r402-25]
R9460  NP  [r402-25]
R9486  0  [r201-6p6spc]
RJ1400  0.A  [JMP402-25]
RJ1401  0.A  [JMP402-25]
RJ1402  0.A  [JMP402-25]
RJ1403  0.A  [JMP402-25]
SW4  PB_SW  [SW4-7914G]
SW6  PB_SW  [SW4-7914G]
TP8153  RD30  [tp-30RD13]
U102  TPS3808G09DBVRG4  [DBV6-27X39-6]
U107  TPS3808G09DBVRG4  [DBV6-27X39-6]
U1400  LP87322ERHDRQ1  [rhd28]
U1401  LP87332ARHDRQ1  [rhd28]
sheet SH21 - POWER MISC SWITCHES
C318  220pF 50V  [c603-35x45]
C319  NP  [c603-35x45]
C8142  NP  [c603-35x45]
C8143  220pF 50V  [c603-35x45]
C8251  0.1uF  [c402-25]
C8252  0.1uF  [c402-25]
C8253  220pF 50V  [c603-35x45]
R9488  10.0K  [r402-25]
R9494  10K  [r402-25]
R9495  1K  [r201-6p6spc]
R9496  1K  [r201-6p6spc]
R9497  NP  [r1206-40X70]
R9498  10K  [r402-25]
R9505  NP  [r201-6p6spc]
SW8002  PB_SW  [SW4-7914G]
TP8067  RD30  [tp-30RD13]
U92  TPS22965DSG  [dsg8-11x20]
U8020  TPS22965DSG  [dsg8-11x20]
U8044  TPS3808G33DBVRG4  [DBV6-27X39-6]
U8045  74LVC1G08DCK  [dck-5]
U8046  SN74LVC2G74DCT  [dct8-14x70]
U8047  TPS22965DSG  [dsg8-11x20]
sheet SH22 - POWER MONITORS
C1029  0.1uF  [c402-25]
C1038  0.1uF  [c402-25]
C1039  0.1uF  [c402-25]
C1041  0.1uF  [c402-25]
C1043  0.1uF  [c402-25]
C1044  0.1uF  [c402-25]
C1045  0.1uF  [c402-25]
C1046  0.1uF  [c402-25]
C1047  0.1uF  [c402-25]
R9178  0.050  [r603-35x45]
R9179  0.050  [r603-35x45]
R9180  NP  [r603-35x45]
R9181  0.050  [r603-35x45]
R9183  0.050  [r603-35x45]
R9188  0.050  [r603-35x45]
R9189  0.050  [r603-35x45]
R9190  0.050  [r603-35x45]
R9348  0.050  [r603-35x45]
R9378  0  [r603-35x45]
R9379  0  [r603-35x45]
R9380  0  [r603-35x45]
R9381  0  [r603-35x45]
R9382  0  [r603-35x45]
R9383  0  [r603-35x45]
U1008  INA226AIDGSR  [dgs10-11x60]
U1017  INA226AIDGSR  [dgs10-11x60]
U1018  NP-INA226AIDGSR  [dgs10-11x60]
U1020  INA226AIDGSR  [dgs10-11x60]
U1022  INA226AIDGSR  [dgs10-11x60]
U1023  INA226AIDGSR  [dgs10-11x60]
U1024  INA226AIDGSR  [dgs10-11x60]
U1025  INA226AIDGSR  [dgs10-11x60]
U1026  INA226AIDGSR  [dgs10-11x60]
sheet SH24 - VOUT LCD CONNECTOR
C8085  NP  [c402-25]
C8184  220uF/0-OHM  [c7343-84x118]
J10  RCA JACK  [rcajack-CUI-RCJ-01]
J15  HEADER 50  [molex-54132-50]
L8005  NP  [l603-35x45]
R636  10K  [r402-25]
R678  10K  [r402-25]
R9194  NP  [r402-25]
R9196  NP  [r402-25]
R9284  0  [r201-6p6spc]
R9285  0  [r201-6p6spc]
R9416  NP  [r402-25]
R9417  NP  [r402-25]
TP52  RD30  [tp-30RD13]
TP8075  RD30  [tp-30RD13]
TP8076  RD30  [tp-30RD13]
TP8077  RD30  [tp-30RD13]
TP8078  RD30  [tp-30RD13]
U8016  NP-OPA360AIDCKRE4  [DCK-17X60-6]

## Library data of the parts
C43 C2003 C2006 C3110 C6000 C6003 C6005 C6007 C6008 C6010 C6012-C6014 C6016 C6017 C6019-C6021 C8050-C8053 C8078 C8251 C8252 = CAP: Part #: 104446-1100R
C6001 C6006 = CAP: Part #: 101782-1274R
C301 C302 C305 C306 C6002 = CAP: Part #: 101587-1101R
C6004 C6009 C6011 C6015 C6018 = CAP: Part #: 101063-0470R
D6000 = LED_0: Part #: 103557-0001R
J6000 = USBMINI_B_0: Part #: 101956-0001R
L6000 L6001 = INDUCTOR: Part #: 101858-6001R
R6000 R6002 R6003 R6007 = R: Part #: 101370-1002R
R765 R6001 = R: Part #: 102145-2401R
R36 R2008 R6004 R9175 = R: Part #: 101370-2202R
R6005 = R: Part #: 102145-1203R
R12 R13 R554 R795 R2019 R6006 R9197 = R: Part #: 101370-0001R
R2011 R2012 R6008-R6011 R9143-R9150 = R: Part #: 101370-2200R
U6000 = TPS73433_1: Part #: 103554-0001R
U6001 = 93C46_3V3: Part #: 103564-0001R
U6002 = TPD2E001_0: Part #: 102728-0001R
U6003 = FT4232H: Part #: 104464-0001R
U6004 U8007 U8008 = SN74AVC4T245RGYR_0: Part #: 102649-0245R
Y6000 = CRYSTAL_9: Part #: 103560-0012R
C59 C441 C499 C8077 = CAP_NP_2: Part #: 104446-1100R
C2000 = CAP: Part #: 100993-1100R
C2001 C2002 C2004 C2005 = CAP_NP_1: Part #: 104446-1100R
C2007 = CAP: Part #: 103497-0100R
C2008 C2009 = CAP: Part #: 104447-0101R
C1029 C1038 C1039 C1041 C1043-C1047 C2010 C2012 = CAP_NP: Part #: 104446-1100R
C2011 = CAP_NP: Part #: 104447-0101R
C2013 C2014 = CAP_NP_3: Part #: 101782-1184R
EXP_P4 = J_-_SamTec_QSH020_40pin_2: Part #: 101881-0020R
L2000-L2002 = FERRITE_CHIP: Part #: 101228-2201R
L2003 = INDUCTOR: Part #: 103631-0470R
P2000 = 66058414_1: Part #: 103166-0001R
R636 R678 R2000-R2003 R2010 R2013-R2016 R9360-R9362 = R: Part #: 101370-1003R
R2004 R2006 R9196 = R: Part #: R0402-NOPOP
R2005 = R: Part #: 102145-1502R
R2007 = R: Part #: 102145-2372R
R2009 R2018 R9344-R9346 = RES_0: Part #: 102145-2401R
R2017 = R: Part #: 102145-4702R
RN2000 = R-Pak4_0: Part #: 101327-2200R
TP52 TP2000 TP8063 TP8065 TP8067 TP8075-TP8078 TP8154 = TESTPOINT: Part #: TP-30RD13-NO-POP
U10 U15 U3102 U8012 U8013 = 1G08: Part #: 101057-0008R
U2000 = AR8031_8: Part #: 103629-0001R
Y2000 = CRYSTAL_0: Part #: 101590-0250R
C45 C49 = CAP_NP: Part #: 100993-1100R
C47 C50 = CAP_NP: Part #: 100201-0100R
C51 = CAP_POL: Part #: 104700-0102R
C52 = CAP_NP: Part #: 103058-0470R
C60 C61 = CAP: Part #: 100993-3303R
C62 C63 = CAP_NP: Part #: 104292-0221R
C71 C74 C683 C689 C690 = C_0: Part #: 104290-0102R
C72 C77 = CAP: Part #: 104294-0471R
C76 C78 = CAP: Part #: 100993-1103R
C295 = CAP: Part #: 103751-0470R
C299 C300 C707 C8248 = CAP: Part #: 103885-1220R
C303 = CAP: Part #: 104291-1202R
C304 = CAP: Part #: 101782-1394R
C307 = CAP: Part #: 102058-1272R
C309 = CAP: Part #: 101782-1564R
C314 = CAP: Part #: 101782-1102R
C684 = CAP: pART #: C1210-NOPOP
C706 = CAP_NP_0: Part #: 101415-0220R
D1 = Diode_SMCJ15CA: Part #: 101808-0030R
D2 = Diode_SMCJ15CA: Part #: 101808-0014R
D6101 = DIODE_0: Part #: NO-POP; Part No.: 102220-0001R
F1 = NANO-SMF_0: Part #: 100872-0004R
J3 = PWR_JACK_0: Part #: 104303-0001R
J4 J7 = HEADER_2: Part #: 100115-0002R
L6 = INDUCTOR: Part #: 104227-0220R
L7 = INDUCTOR: Part #: 104288-0820R
Q1-Q5 = MOSFET_CSD16406Q3_0: Part #: 104283-0001R
R126 R127 = RESISTOR: Part #: 100687-1000R
R134 = RESISTOR: Part #: 104280-0005R
R135 = RESISTOR: Part #: 100830-0015R
R143 R147 = RESISTOR: Part #: 102145-4990R
R144 = RESISTOR: Part #: 100642-4993R
R145 R472 = RESISTOR: Part #: 102145-1603R
R146 = RESISTOR: Part #: 100642-8453R
R450 R451 R455-R457 R463 = RESISTOR: Part #: 101370-0001R
R453 = RESISTOR: Part #: 102145-1502R
R454 = RESISTOR: Part #: R0402-NOPOP
R461 = RESISTOR: Part #: 102145-2003R
R464 = RESISTOR: Part #: 102145-1503R
R810 = R_2: Part #: 101370-1002R
R9461 = 10KOhmResistor1_16W0402: Part #: 101370-1003R
R9464 R9466 = R: Part #: 100642-6193R
R9465 = R: Part #: 100642-8453R
SW4 SW6 SW9 SW8002 = SW_PUSHBUTTON_3: Part #: 101023-0001R
TP823-TP830 TP8142 = SMT-TP: Part #: 104178-0001R
U8 = LM74610: Part #: 104635-0001R
U23 = TPS43351QDAPRQ1_0: Part #: 104224-0001R
C421 C476 = CAP_NP_2: Part #: 101782-1223R
C1400 C1402 C1415 C1417 = CAP_0402_1uF_X7R_6.3V_10%_X_SD: Part #: 104723-0100R; SIZE: 0603
C1401 C1416 = CAP_0402_0.1uf_x7r_16v_10%_X_SD: Part #: 104446-1100R
C1403 C1404 C1413 C1414 = CAP_0603_2.2uf_x7r_10v_10%_X_sd: Part #: 104720-0220R; SIZE: 0805
C1405 C1406 C1411 C1412 = CAP_0805_10uF_X7R_10V_10%_X_SD: Part #: 104721-0101R; RATING: 16V; SIZE: 1206
C1407-C1410 = CAP_0805_22uF_X7R_6.3V_20%_X_SD: Part #: 104463-0221R; SIZE: 1206
DS5 = LED_RED_0: Part #: 100823-0001R
L1400-L1403 = IND_1008_0.47uH_6A_20%_X_SD: Part #: 104717-1470R
Q2033 = MOSFET_N_1_v2: Part #: 100680-0001R
R583 R616 = RESISTOR: Part #: 101370-1003R
R596 R623 = R_2: Part #: 101370-1003R
R670 R9486 = R: Part #: 103158-0001R
R1404 R1415 R9488 = RES_0402_10k_1.0%_0.063W_X_SD: Part #: 102145-1003R
R1405 R1414 R1417 R9457 R9458 = RES_0402_0_1.0A_0.063W_X_SD: Part #: 101370-0001R
R1408 R1409 R1412 R1413 = RES_0603_0.02_1%_2.2A_0.1W_X_SD: Part #: 103258-0002R
R9387 = R_0: Part #: 102145-2401R
R9459 R9460 = RES_0402_10k_1.0%_0.063W_X_SD: Part #: R0402-NOPOP
RJ1400-RJ1403 = RJUMP3: Part #: 101370-0001R
TP8153 = TESTPOINT_1: Part #: TP-30RD13-NO-POP
U102 U107 = TPS3808G09DBVR_0: Part #: 102020-0009R
U1400 = IC_LP8732Q1_QFN28_X_SD: Part #: 104714-1135R-TI
U1401 = IC_LP8733Q1_QFN28_X_SD: Part #: 104715-0001R-TI
C318 C8143 C8253 = CAP: Part #: 100993-1223R
C319 C8142 = CAP: Part #: C0603-NOPOP
R9494 R9498 = R: Part #: 102145-1003R
R9495 R9496 = R: Part #: 103158-1002R
R9497 = R: Part #: r1206-nopop
R9505 = R: Part #: r0201-nopop
U92 U8020 U8047 = TPS22965DSG: Part #: 104267-0001R
U8044 = TPS3808G09DBVR_0: Part #: 102020-0033R
U8045 = 1G08_0: Part #: 101057-0008R
U8046 = SN74LVC2G74DCT: Part #: 103304-0001R
R9178 R9179 R9181 R9183 R9188-R9190 R9348 = R: Part #: 104469-0005R
R9180 = R: Part #: R0603-NOPOP
R9378-R9383 = R: Part #: 100687-0001R
U1008 U1017 U1020 U1022-U1026 = INA220IDCN_2: Part #: 103928-0001R
U1018 = INA220IDCN_2: Part #: NO-POP
C8085 = CAP: Part #: C0402-NOPOP
C8184 = C_0: Part #: 100757-0001R
J10 = RCA_JACK_0: Part #: 102540-0014R
J15 = HEADER_50: Part #: 103716-0050R
L8005 = FERRITE_CHIP_0: Part #: L0603-NOPOP
R9194 R9416 R9417 = R_0: Part #: R0402-NOPOP
R9284 R9285 = R_1: Part #: 103158-0001R
U8016 = OPA360: Part #: NO-POP

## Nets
AVDD3V3_ENET0: C2003.1 C2008.1 L2000.2 U2000.16(AVDD33.1)
DVDDL_ENET0: C2011.1 C2012.1 L2002.2 L2003.1 R2017.1 U2000.47(DVDDL)
GND: C43.2 C45.2 C47.2 C49.2 C50.2 C51.2 C52.2 C59.2 C60.1 C61.1 C62.1 C63.1 C71.2 C72.2 C74.2 C76.1 C77.2 C78.1 C295.1 C304.1 C305.2 C306.2 C309.1 C314.2 C318.2 C319.2 C421.2 C441.2 C476.2 C499.2 C683.2 C684.2 C689.2 C690.2 C707.2 C1029.1 C1038.1 C1039.1 C1041.1 C1043.1 C1044.1 C1045.1 C1046.1 C1047.1 C1400.2 C1401.2 C1402.2 C1403.2 C1404.2 C1405.2 C1406.2 C1407.2 C1408.2 C1409.2 C1410.2 C1411.2 C1412.2 C1413.2 C1414.2 C1415.2 C1416.2 C1417.2 C2000.2 C2001.2 C2002.2 C2003.2 C2004.2 C2005.2 C2006.2 C2007.2 C2008.2 C2009.2 C2010.1 C2011.2 C2012.2 C2013.2 C2014.2 C3110.2 C6000.2 C6001.2 C6002.2 C6003.2 C6004.2 C6005.2 C6006.2 C6007.2 C6008.2 C6009.2 C6010.2 C6011.2 C6012.2 C6013.2 C6014.2 C6015.2 C6016.2 C6017.2 C6018.2 C6019.2 C6020.2 C6021.2 C8050.2 C8051.2 C8052.2 C8053.2 C8077.2 C8078.2 C8085.2 C8142.2 C8143.2 C8248.2 C8251.2 C8252.2 C8253.2 D2.1(CATHODE) EXP_P4.17 EXP_P4.18 EXP_P4.41(G1) EXP_P4.42(G2) EXP_P4.43(G3) EXP_P4.44(G4) J3.2 J3.MTG1 J3.MTG2 J4.1 J7.2 J10.1(SHIELD) J10.3(SHIELD3) J10.4(SHIELD4) J15.13 J15.18 J15.27 J15.36 J15.45 J15.50 J6000.5(USBVSS) P2000.1(GND) P2000.11(SHLD1) P2000.12(SHLD2) P2000.D2(LED1-K) Q3.1(S1) Q3.2(S2) Q3.3(S3) Q4.1(S1) Q4.2(S2) Q4.3(S3) Q2033.S R145.1 R455.1 R461.1 R463.1 R464.1 R472.1 R636.2 R810.2 R2000.1 R2001.1 R2002.1 R2003.1 R2007.1 R2010.1 R2013.2 R2014.2 R2015.2 R2016.2 R6005.1 R6006.1 R9416.2 R9466.1 R9496.2 SW4.1(A) SW4.2(AA) SW6.1(A) SW6.2(AA) SW8002.1(A) SW8002.2(AA) TP823.1 TP824.1 TP825.1 TP826.1 TP827.1 TP828.1 TP829.1 TP830.1 TP8142.1 U10.3(GND) U15.3(GND) U23.9(PGNDA) U23.19(AGND.1) U23.23(AGND.2) U23.30(PGNDB) U23.39(PWR_PAD) U92.5(GND) U92.9(PWR_PAD) U102.2(GND) U107.2(GND) U1008.7(GND) U1017.7(GND) U1018.1(A1) U1018.2(A0) U1018.7(GND) U1020.1(A1) U1020.7(GND) U1022.1(A1) U1022.7(GND) U1023.7(GND) U1024.1(A1) U1024.7(GND) U1025.2(A0) U1025.7(GND) U1026.7(GND) U1400.4(AGND) U1400.15(PGND1_B1) U1400.16(PGND2_B1) U1400.19(SGND) U1400.20(PGND1_B0) U1400.21(PGND2_B0) U1400.29(TPAD) U1401.4(AGND) U1401.15(PGND1_B1) U1401.16(PGND2_B1) U1401.19(SGND) U1401.20(PGND1_B0) U1401.21(PGND2_B0) U1401.29(TPAD) U2000.49(PWRPAD) U3102.3(GND) U6000.3(GND) U6000.7(GND) U6001.2(GND) U6002.4(GND) U6003.1(GND) U6003.5(GND) U6003.10(AGND) U6003.11(GND) U6003.13(TEST) U6003.15(GND) U6003.25(GND) U6003.35(GND) U6003.47(GND) U6003.51(GND) U6004.3(2DIR) U6004.8(GND.1) U6004.9(GND.2) U6004.14(2~{OE}) U6004.15(1~{OE}) U6004.17(GND.3) U8007.3(2DIR) U8007.8(GND.1) U8007.9(GND.2) U8007.14(2~{OE}) U8007.15(1~{OE}) U8007.17(GND.3) U8008.3(2DIR) U8008.8(GND.1) U8008.9(GND.2) U8008.14(2~{OE}) U8008.15(1~{OE}) U8008.17(GND.3) U8012.3(GND) U8013.3(GND) U8016.2(GND) U8020.5(GND) U8020.9(PWR_PAD) U8044.2(GND) U8045.3(GND) U8046.2(D) U8046.4(GND) U8047.5(GND) U8047.9(PWR_PAD) Y6000.2(NC1) Y6000.4(NC2) ; also on sheet 4 5 6 7 8 9 17 18 19 20 21 22 23 25 26 27 28 29 30 31 32 34 35 36 37
VDD3V3_ENET0: C2006.1 C2009.1 L2001.2 U2000.4(VDD33.1)
VDD_DDR_CPU: R9497.1 U8047.7(VOUT.2) U8047.8(VOUT.1) ; also on sheet 37
VDD_SHV: R9180.2 R9181.2 R9348.1 R9378.1 R9379.1 R9380.1 R9381.1 R9382.1 R9383.1 U1018.9(VIN-) U1020.9(VIN-) U1022.8(VBUS) U1022.10(VIN+) ; also on sheet 5 7
VDDA_ANA_1V8: R9189.2 U1008.9(VIN-) ; also on sheet 4 5
VDDA_DPLL_1V8: R9188.2 U1017.9(VIN-) ; also on sheet 5
VDDH_REG: C2007.1 R2004.1 R2005.1 R2006.1 R9197.2 U2000.10(VDDH_REG)
VDDIO_REG_ENET0: C2000.1 R9197.1 U2000.29(VDDIO_REG)
VDDS_1V8: R9178.2 U1026.9(VIN-) ; also on sheet 5
VDDS_DDR_1V8: R9179.2 U1025.9(VIN-) ; also on sheet 5
VDDS_GEN_DV: R9378.2 ; also on sheet 5
VDDS_GPMC_DV: R9379.2 ; also on sheet 5
VDDS_MMC4_DV: R9380.2 ; also on sheet 5
VDDS_RGMII_DV: R9381.2 ; also on sheet 5
VDDS_VIN_DV: R9382.2 ; also on sheet 5
VDDS_VOUT_DV: R9383.2 ; also on sheet 5
VIN_12V: F1.2 J3.1
ADVDDL_ENET0: C2001.1 C2002.1 C2004.1 C2005.1 L2002.1 U2000.8(AVDDL.1) U2000.13(AVDDL.2) U2000.19(AVDDL.3) U2000.44(AVDDL.4)
APP_BD_PORz: Q2033.G R670.2 TP8153.1(TP) ; also on sheet 9
BUTTON_PORZ: R583.2 SW4.3(B) SW4.4(BB) U102.3(~{MR})
BUTTON_RESET: R616.2 R9486.2 SW6.3(B) SW6.4(BB) U107.3(~{MR})
CON_LCD_PWR_DN: J15.14 R678.2 ; also on sheet 8
CVIDEO_TVOUT: C8184.1 R9417.1 ; also on sheet 4
EMU_RSTn: R9486.1 ; also on sheet 31
EN_SW3V3_VPO5V0: R9488.1 TP8067.1(TP) U92.3(ON) U1401.26(GPO1) U8020.3(ON)
ENET0_INTn: R2008.2 U15.1(B) U2000.5(INT)
ENET0_RSTn: R9344.2 U3102.4(Y)
ENET1_RSTn: EXP_P4.15 R9346.1
ENET2_RSTn: R9345.2 U8013.4(Y)
ENET_INTSn: R765.1 ; also on sheet 7 34
ENET_PORz: R795.2 U10.1(B) U3102.1(B) U8013.1(B)
FB_VPO_S1_AVS: RJ1403.1 ; also on sheet 37
FB_VPO_S2_AVS: RJ1402.1 ; also on sheet 37
FB_VPO_S3_1V8: RJ1400.1 ; also on sheet 37
FB_VPO_S4_DV: RJ1401.1 ; also on sheet 37
FTDI_TCK: U6003.48(DDBUS0/TXD) ; also on sheet 27
FTDI_TDI: U6003.52(DDBUS1/RXD) ; also on sheet 27
FTDI_TDO: U6003.53(DDBUS2/RTS#) ; also on sheet 27
FTDI_TMS: U6003.54(DDBUS3/CTS#) ; also on sheet 27
GA1: R451.2 U23.6(GA1)
GA2: R457.2 U23.8(GA2)
GB1: R450.2 U23.33(GB1)
GB2: R456.2 U23.31(GB2)
IOEXP2_P12: R9360.2 U3102.2(A) ; also on sheet 8
IOEXP2_P13: R9362.2 U10.2(A) ; also on sheet 8
IOEXP2_P14: R9361.2 U8013.2(A) ; also on sheet 8
LCD_B0: J15.37 ; also on sheet 26
LCD_B1: J15.38 ; also on sheet 26
LCD_B2: J15.39 ; also on sheet 26
LCD_B3: J15.40 ; also on sheet 26
LCD_B4: J15.41 ; also on sheet 26
LCD_B5: J15.42 ; also on sheet 26
LCD_B6: J15.43 ; also on sheet 26
LCD_B7: J15.44 ; also on sheet 26
LCD_DE: J15.46 TP8075.1(TP) ; also on sheet 26
LCD_G0: J15.28 ; also on sheet 26
LCD_G1: J15.29 ; also on sheet 26
LCD_G2: J15.30 ; also on sheet 26
LCD_G3: J15.31 ; also on sheet 26
LCD_G4: J15.32 ; also on sheet 26
LCD_G5: J15.33 ; also on sheet 26
LCD_G6: J15.34 ; also on sheet 26
LCD_G7: J15.35 ; also on sheet 26
LCD_HS: J15.47 TP8076.1(TP) ; also on sheet 26
LCD_PCLK: J15.49 TP8078.1(TP) ; also on sheet 26
LCD_R0: J15.19 ; also on sheet 26
LCD_R1: J15.20 ; also on sheet 26
LCD_R2: J15.21 ; also on sheet 26
LCD_R3: J15.22 ; also on sheet 26
LCD_R4: J15.23 ; also on sheet 26
LCD_R5: J15.24 ; also on sheet 26
LCD_R6: J15.25 ; also on sheet 26
LCD_R7: J15.26 ; also on sheet 26
LCD_VS: J15.48 TP8077.1(TP) ; also on sheet 26
LP32_GPO: U1400.26(GPO1) ; also on sheet 6
LP32_INTn: R1404.1 R1405.1 U1400.9(INTn)
LP33_INTn: R1414.1 R1415.1 U1401.9(INTn)
LP_INTn: R1405.2 R1414.2 ; also on sheet 32
MFB1_RGMII0_RXC: R2012.1 R2016.1 ; also on sheet 34
MFB1_RGMII0_RXCTL: R2010.2 R2011.1 ; also on sheet 34
MFB1_RGMII0_RXD0: R2003.2 RN2000.8(R1B) ; also on sheet 34
MFB1_RGMII0_RXD1: R2002.2 RN2000.7(R2B) ; also on sheet 34
MFB1_RGMII0_RXD2: R2001.2 RN2000.6(R3B) ; also on sheet 34
MFB1_RGMII0_RXD3: R2000.2 RN2000.5(R4B) ; also on sheet 34
MFB1_RGMII0_TXC: U2000.35(GTX_CLK) ; also on sheet 34
MFB1_RGMII0_TXCTL: U2000.34(TX_EN) ; also on sheet 34
MFB1_RGMII0_TXD0: U2000.36(TXD0) ; also on sheet 34
MFB1_RGMII0_TXD1: U2000.37(TXD1) ; also on sheet 34
MFB1_RGMII0_TXD2: U2000.38(TXD2) ; also on sheet 34
MFB1_RGMII0_TXD3: U2000.39(TXD3) ; also on sheet 34
MFB2_RGMII0_RXC: EXP_P4.40 ; also on sheet 34
MFB2_RGMII0_RXCTL: EXP_P4.37 ; also on sheet 34
MFB2_RGMII0_RXD0: EXP_P4.38 ; also on sheet 34
MFB2_RGMII0_RXD1: EXP_P4.35 ; also on sheet 34
MFB2_RGMII0_RXD2: EXP_P4.36 ; also on sheet 34
MFB2_RGMII0_RXD3: EXP_P4.33 ; also on sheet 34
MFB2_RGMII0_TXC: EXP_P4.34 ; also on sheet 34
MFB2_RGMII0_TXCTL: EXP_P4.31 ; also on sheet 34
MFB2_RGMII0_TXD0: EXP_P4.32 ; also on sheet 34
MFB2_RGMII0_TXD1: EXP_P4.29 ; also on sheet 34
MFB2_RGMII0_TXD2: EXP_P4.30 ; also on sheet 34
MFB2_RGMII0_TXD3: EXP_P4.27 ; also on sheet 34
MHB1_UART3_CTSn: R9150.2 ; also on sheet 34
MHB1_UART3_RTSn: U8008.10(2B2) ; also on sheet 34
MHB1_UART3_RXD: R9149.2 ; also on sheet 34
MHB1_UART3_TXD: U8008.11(2B1) ; also on sheet 34
MJB2_UART2_CTSn: R9146.2 ; also on sheet 32
MJB2_UART2_RTSn: U8007.10(2B2) ; also on sheet 32
MJB2_UART2_RXD: R9145.2 ; also on sheet 32
MJB2_UART2_TXD: U8007.11(2B1) ; also on sheet 32
MKB1_UART1_CTSn: R6010.2 ; also on sheet 32
MKB1_UART1_RTSn: U6004.10(2B2) ; also on sheet 32
MKB1_UART1_RXD: R6009.2 ; also on sheet 32
MKB1_UART1_TXD: U6004.11(2B1) ; also on sheet 32
MMB1_RGMII1_RXC: EXP_P4.16 ; also on sheet 32
MMB1_RGMII1_RXCTL: EXP_P4.13 ; also on sheet 32
MMB1_RGMII1_RXD0: EXP_P4.14 ; also on sheet 32
MMB1_RGMII1_RXD1: EXP_P4.11 ; also on sheet 32
MMB1_RGMII1_RXD2: EXP_P4.12 ; also on sheet 32
MMB1_RGMII1_RXD3: EXP_P4.9 ; also on sheet 32
MMB1_RGMII1_TXC: EXP_P4.10 ; also on sheet 32
MMB1_RGMII1_TXCTL: EXP_P4.7 ; also on sheet 32
MMB1_RGMII1_TXD0: EXP_P4.8 ; also on sheet 32
MMB1_RGMII1_TXD1: EXP_P4.5 ; also on sheet 32
MMB1_RGMII1_TXD2: EXP_P4.6 ; also on sheet 32
MMB1_RGMII1_TXD3: EXP_P4.3 ; also on sheet 32
P0_LED_ACT: R2004.2 R2009.2 R2015.1 U2000.23(LED_ACT)
P0_LED_LINK10_100: R2013.1 R2019.1 U2000.26(LED_LINK10_100)
P0_LED_LINK1000: R2014.1 R2018.2 U2000.24(LED_LINK1000)
PB_ON: D6101.2(ANODE) J4.2 R9464.2 R9465.1 R9466.2 SW9.3(B) SW9.4(BB) ; also on sheet 28 29
PHA: C300.1 L6.1 Q1.1(S1) Q1.2(S2) Q1.3(S3) Q3.5(D1) R126.2 U23.7(PHA)
PHB: C299.1 L7.1 Q2.1(S1) Q2.2(S2) Q2.3(S3) Q4.5(D1) R127.2 U23.32(PHB)
PM2_SCL: U1008.5(SCL) U1017.5(SCL) U1018.5(SCL) U1020.5(SCL) U1022.5(SCL) U1023.5(SCL) U1024.2(A0) U1024.5(SCL) U1025.5(SCL) U1026.2(A0) U1026.5(SCL) ; also on sheet 29
PM2_SDA: U1008.1(A1) U1008.2(A0) U1008.4(SDA) U1017.1(A1) U1017.4(SDA) U1018.4(SDA) U1020.4(SDA) U1022.2(A0) U1022.4(SDA) U1023.2(A0) U1023.4(SDA) U1024.4(SDA) U1025.1(A1) U1025.4(SDA) U1026.4(SDA) ; also on sheet 29
PMIC_REGEN_DDR: R9498.2 U1400.10(CLKIN/GPO2) U8047.3(ON) ; also on sheet 6
PORz: R596.1 R670.1 R795.1 R1417.2 U102.1(~{RESE}T) U1400.27(PGOOD) U1401.27(PGOOD) ; also on sheet 4 26 27
POWERHOLD: U1400.6(EN) U1401.6(EN) U8045.4(Y)
POWERHOLD_CLK: R9505.1 ; also on sheet 8
PWR_GD_PBUCK: R9461.2(P2) TP8063.1(TP) U23.15(PGA) U23.24(PGB) U8045.2(A)
R_I2C1_SCL: R9458.2 ; also on sheet 7 8 28 29 36
R_I2C1_SDA: R9457.2 ; also on sheet 7 8 28 29 36
RESETn: R623.1 U107.1(~{RESE}T) ; also on sheet 4
RGB1_MDIO_D: R2005.2 U2000.48(MDIO) ; also on sheet 34
RGB1_MDIO_MCLK: R2006.2 U2000.1(MDC) ; also on sheet 34
RGB2_MDIO_D: EXP_P4.2 ; also on sheet 34
RGB2_MDIO_MCLK: EXP_P4.1 ; also on sheet 34
RST_CT_PORZ: C421.1 U102.4(CT)
RST_CT_RESET: C476.1 U107.4(CT)
RST_SENSE: R554.2 U102.5(SENSE1) U107.5(SENSE1)
TS_LCD_GPIO1: J15.9 ; also on sheet 8
TS_LCD_GPIO2: J15.10 ; also on sheet 8
TS_LCD_GPIO3: J15.11 ; also on sheet 8
TS_LCD_GPIO4: J15.12 ; also on sheet 8
TS_LCD_IRQ: J15.15 R636.1 TP52.1(TP) ; also on sheet 26
USART_A_CTS: R6008.1 U6003.19(ADBUS3/CTS#/TMS)
USART_A_CTS_R: R6008.2 U6004.7(2A2)
USART_A_RTS: U6003.18(ADBUS2/RTS#/TDO) U6004.5(1A2)
USART_A_RXD: R6011.1 U6003.17(ADBUS1/RXD/TDI)
USART_A_RXD_R: R6011.2 U6004.6(2A1)
USART_A_TXD: U6003.16(ADBUS0/TXD/TCK) U6004.4(1A1)
USART_B_CTS: R9144.1 U6003.29(BCBUS3/CTS#/TMS)
USART_B_RTS: U6003.28(BCBUS2/RTS#/TDO) U8007.5(1A2)
USART_B_RXD: R9143.1 U6003.27(BCBUS1/RSC/TDI)
USART_B_TXD: U6003.26(BCBUS0/TXD/TCK) U8007.4(1A1)
USART_C_CTS: R9148.1 U6003.41(CDBUS3/CTS#)
USART_C_RTS: U6003.40(CDBUS2/RTS#) U8008.5(1A2)
USART_C_RXD: R9147.1 U6003.39(CDBUS1/RXD)
USART_C_TXD: U6003.38(CDBUS0/TXD) U8008.4(1A1)
USART_DM: J6000.2(D-) U6002.5(IO2) U6003.7(USBDM)
USART_DP: J6000.3(D+) U6002.3(IO1) U6003.8(USBDP)
USART_EECS: R6002.1 U6001.5(CS) U6003.63(EECS)
USART_EEDIN: R6004.2 U6001.3(DIN) U6003.61(EEDATA)
USART_EEDOUT: R6003.1 R6004.1 U6001.1(DO)
USART_EESK: R6000.1 U6001.4(CLK) U6003.62(EESK)
USART_GND: J6000.6(SHIELD1) J6000.7(SHIELD2) J6000.8(SHIELD3) J6000.9(SHIELD4) R6006.2
USART_LED: D6000.1(A) R6001.2
USART_NR: C6002.1 U6000.2(NR)
USART_OSCI: C6001.1 U6003.2(OSCI) Y6000.1
USART_OSCO: C6006.1 U6003.3(OSCO) Y6000.3
USART_PWREN: D6000.2(C) U6003.60(PWREN#)
USART_RESETn: R6007.2 U6003.14(RESET#)
USART_RSET: R6005.2 U6003.6(REF)
V_U8016: C8085.1 L8005.1 U8016.6(V+)
VBUCK_3V3: C71.1 C74.1 C302.2 C683.1 C689.1 C690.1 C1029.2 C1038.2 C1039.2 C1041.2 C1043.2 C1044.2 C1045.2 C1046.2 C1047.2 R134.1 R143.2 U23.11(SA2) U1008.6(VS) U1017.2(A0) U1017.6(VS) U1018.6(VS) U1020.2(A0) U1020.6(VS) U1022.6(VS) U1023.1(A1) U1023.6(VS) U1024.6(VS) U1025.6(VS) U1026.1(A1) U1026.6(VS) ; also on sheet 29 37
VBUCK_5V0: C72.1 C77.1 C301.2 C684.1 R135.1 R147.2 U23.28(SB2) ; also on sheet 37
VLIM_12V: Q5.5(D1) R453.2 R9465.2 U8.8(CATHODE) ; also on sheet 28 37
VOUT_I2C_SCL: R9285.2 ; also on sheet 7 17 31
VOUT_I2C_SDA: R9284.2 ; also on sheet 7 17 31
VPHY_USART: C6011.1 C6012.1 L6000.1 U6003.4(VPHY)
VPIN_S1_3V3: C1411.1 R1412.1 U1401.24(VIN1_B0) U1401.25(VIN2_B0) ; also on sheet 37
VPIN_S2_3V3: C1412.1 R1413.1 U1401.11(VIN1_B1) U1401.12(VIN2_B1) ; also on sheet 37
VPIN_S3_3V3: C1406.1 R1409.1 U1400.24(VIN1_B0) U1400.25(VIN2_B0) ; also on sheet 37
VPIN_S4_3V3: C1405.1 R1408.1 U1400.11(VIN1_B1) U1400.12(VIN2_B1) ; also on sheet 37
VPLL_USART: C6014.1 C6015.1 L6001.1 U6003.9(VPLL)
VPO_1V8: R9178.1 R9179.1 R9180.1 R9190.1 U1018.8(VBUS) U1018.10(VIN+) U1023.8(VBUS) U1023.10(VIN+) U1025.8(VBUS) U1025.10(VIN+) U1026.8(VBUS) U1026.10(VIN+) ; also on sheet 4 37
VPO_DDR_DV: R9497.2 U8047.1(VIN.1) U8047.2(VIN.2) ; also on sheet 37
VPO_L2_xVx: C1417.1 U1401.7(VOUT_LDO1)
VPO_L3_xVx: C1402.1 U1400.1(VOUT_LDO0)
VPO_L4_xVx: C1400.1 U1400.7(VOUT_LDO1)
VPO_L5_1V8: C1415.1 R9188.1 R9189.1 U1008.8(VBUS) U1008.10(VIN+) U1017.8(VBUS) U1017.10(VIN+) U1401.1(VOUT_LDO0)
VPO_S1_AVS: C1409.1 L1402.1(P1) RJ1403.3 ; also on sheet 37
VPO_S1_SW: L1402.2(P2) U1401.22(SW1_B0) U1401.23(SW2_B0)
VPO_S2_AVS: C1410.1 L1403.1(P1) RJ1402.3 ; also on sheet 37
VPO_S2_SW: L1403.2(P2) U1401.13(SW1_B1) U1401.14(SW2_B1)
VPO_S3_1V8: C1408.1 L1401.1(P1) RJ1400.3 ; also on sheet 37
VPO_S3_SW: L1401.2(P2) U1400.22(SW1_B0) U1400.23(SW2_B0)
VPO_S4_DV: C1407.1 L1400.1(P1) RJ1401.3 ; also on sheet 37
VPO_S4_SW: L1400.2(P2) U1400.13(SW1_B1) U1400.14(SW2_B1)
VPRH_1V8: J15.7 J15.8 R9190.2 R9488.2 R9498.1 U1023.9(VIN-) ; also on sheet 6 20 21 22
VPRH_3V3: EXP_P4.19 EXP_P4.21 J15.4 J15.5 J15.6 L2000.1 L2001.1 R9183.2 U1024.9(VIN-) ; also on sheet 8 9 17 18 19 20 21 22 23 25 30 31 32 34 35
VPRH_5V0: C8142.1 J15.1 J15.2 J15.3 U8020.7(VOUT.2) U8020.8(VOUT.1) ; also on sheet 17 20 21 23 25 26 35
VPRH_DV: C43.1 C59.1 C3110.1 C6021.1 C8051.1 C8053.1 C8077.1 C8078.1 EXP_P4.20 EXP_P4.22 R36.1 R596.2 R623.2 R678.1 R1404.2 R1415.2 R2008.1 R9175.1 R9348.2 R9360.1 R9361.1 R9362.1 R9459.2 R9460.2 U10.5(VCC) U15.5(VCC) U1022.9(VIN-) U3102.5(VCC) U6004.16(VCCB) U8007.16(VCCB) U8008.16(VCCB) U8012.5(VCC) U8013.5(VCC) ; also on sheet 4 7 8 9 17 18 19 20 21 22 23 26 27 28 31 35 36
VSW_3V3: C319.1 R9181.1 R9183.1 U92.7(VOUT.2) U92.8(VOUT.1) U1020.8(VBUS) U1020.10(VIN+) U1024.8(VBUS) U1024.10(VIN+)
VSYS_3V3: C441.1 C499.1 C1401.1 C1403.1 C1404.1 C1413.1 C1414.1 C1416.1 C8251.1 C8252.1 L8005.2 R554.1 R583.1 R616.1 R1408.2 R1409.2 R1412.2 R1413.2 R9196.2 R9387.1 R9461.1(P1) R9494.1 R9495.1 U92.1(VIN.1) U92.2(VIN.2) U102.6(VDD) U107.6(VDD) U1400.5(VANA) U1400.8(VIN_LDO1) U1400.28(VIN_LDO0) U1401.5(VANA) U1401.8(VIN_LDO1) U1401.28(VIN_LDO0) U8044.5(SENSE1) U8044.6(VDD) U8045.5(VCC) U8046.6(CLR) U8046.8(VCC) ; also on sheet 6 26 27 32 37
VSYS_5V0: U92.4(VBIAS) U8020.1(VIN.1) U8020.2(VIN.2) U8020.4(VBIAS) U8047.4(VBIAS) ; also on sheet 30 32 34 37
VSYS_12V: C45.1 C47.1 C49.1 C50.1 C51.1 C52.1 C62.2 C63.2 J7.1 Q1.5(D1) Q2.5(D1) U23.38(VIN) ; also on sheet 29 37
VUSART_1V8: C6007.1 C6009.1 C6016.1 C6017.1 U6003.12(VCORE) U6003.37(VCORE) U6003.49(VREGOUT) U6003.64(VCORE)
VUSART_3V3: C6000.1 C6005.1 C6008.1 C6010.1 C6013.1 C6018.1 C6019.1 C6020.1 C8050.1 C8052.1 L6000.2 L6001.2 R6000.2 R6002.2 R6003.2 R6007.1 U6000.1(VOUT) U6001.6(VCC) U6003.20(VCCIO) U6003.31(VCCIO) U6003.42(VCCIO) U6003.50(VREGIN) U6003.56(VCCIO) U6004.1(VCCA) U6004.2(1DIR) U8007.1(VCCA) U8007.2(1DIR) U8008.1(VCCA) U8008.2(1DIR)
VUSART_VBUS: C6003.1 C6004.1 J6000.1(USBVDD) R6001.1 U6000.4(EN) U6000.6(VIN) U6002.1(VCC)
N16916234: TP8154.1(TP) U23.4(GC2)
N17182110: R13.2 U23.16(ENA)
N17182418: R12.2 U23.17(ENB)
N17182487: C8248.1 D6101.1(CATHODE) R12.1 R13.1 R9464.1
N17213676: R463.2 U23.22(RT)
N17213686: C60.2 R126.1
N17213736: C61.2 R127.1
N17213790: C299.2 U23.34(CBB)
N17213830: C78.2 R145.2 R146.1 U23.27(FBB)
N17213836: C303.2 C304.2 U23.26(COMPB)
N17213838: C301.1 L7.2 R135.2 U23.29(SB1)
N17213987: C295.2 R454.2 U23.35(VREG)
N17214057: Q2.4(G) R450.1
N17214061: R146.2 R147.1
N17214151: C300.2 U23.5(CBA)
N17214195: C76.2 R144.1 R472.2 U23.12(FBA)
N17214201: C307.2 C309.2 U23.13(COMPA)
N17214229: C302.1 L6.2 R134.2 U23.10(SA1)
N17214255: R454.1 R455.2 U23.20(SYNC)
N17214311: C305.1 U23.14(SSA)
N17214457: R453.1 U23.1(VBAT)
N17214562: C314.1 U23.21(DLYAB)
N17214601: Q1.4(G) R451.1
N17214615: C306.1 U23.25(SSB)
N17214651: R143.1 R144.2
N17517274: J15.17 R9285.1
N18946255: J15.16 R9284.1
N24526186: R810.1 SW9.1(A) SW9.2(AA)
N24574131: RN2000.4(R4A) U2000.27(RXD3)
N24574133: RN2000.3(R3A) U2000.28(RXD2)
N24574135: RN2000.2(R2A) U2000.30(RXD1)
N24574137: RN2000.1(R1A) U2000.31(RXD0)
N24574166: TP8065.1(TP) U2000.25(CLK_125M)
N24574168: C2014.1 U2000.7(XTLI) Y2000.2
N24574174: C2013.1 U2000.6(XTLO) Y2000.1
N24574190: R2017.2 U2000.41(SD)
N24574198: R2007.2 U2000.9(RBIAS)
N24574242: P2000.9(T0+) U2000.11(TRXP0)
N24574244: P2000.10(T0-) U2000.12(TRXN0)
N24574250: P2000.7(T1+) U2000.14(TRXP1)
N24574256: P2000.8(T1-) U2000.15(TRXN1)
N24574262: P2000.5(T2+) U2000.17(TRXP2)
N24574268: P2000.6(T2-) U2000.18(TRXN2)
N24574274: P2000.3(T3+) U2000.20(TRXP3)
N24574280: P2000.4(T3-) U2000.21(TRXPN3)
N24574341: P2000.D1(LED1-A) R2009.1
N24574351: P2000.D4(LED2-KA) R2019.2
N24574361: P2000.D3(LED2-AK) R2018.1
N24574386: C2010.2 P2000.2(VCC) TP2000.1(TP)
N24574466: L2003.2 U2000.3(LX)
N24575043: R2011.2 U2000.32(RX_DV)
N24575045: R2012.2 U2000.33(RX_CLK)
N24577187: R765.2 U15.4(Y)
N24577232: R9346.2 U10.4(Y)
N24605978: EXP_P4.4 R36.2 U8012.2(A)
N25260507: R6009.1 U6004.13(1B1)
N25260509: R6010.1 U6004.12(1B2)
N25262023: R9143.2 U8007.6(2A1)
N25262056: R9144.2 U8007.7(2A2)
N25262058: R9145.1 U8007.13(1B1)
N25262060: R9146.1 U8007.12(1B2)
N25262573: R9147.2 U8008.6(2A1)
N25262606: R9148.2 U8008.7(2A2)
N25262608: R9149.1 U8008.13(1B1)
N25262610: R9150.1 U8008.12(1B2)
N25470528: EXP_P4.39 R9345.1
N25476746: U15.2(A) U8012.4(Y)
N25476918: EXP_P4.28 R9175.2 U8012.1(B)
N26387990: C8143.1 U8020.6(CT)
N26552509: R9344.1 U2000.2(RSTn)
N28609730: C8184.2 J10.2(CENTER) R9194.2
N28609924: R9194.1 U8016.3(SAG) U8016.4(OUT)
N28609984: R9196.1 U8016.5(ENABLE)
N28610283: R9416.1 R9417.2 U8016.1(+IN)
N30048773: R9458.1 R9460.1 U1400.17(SCL) U1401.17(SCL)
N30048775: R9457.1 R9459.1 U1400.18(SDA) U1401.18(SDA)
N30048874: RJ1403.2 U1401.2(FB_B0)
N30048893: RJ1402.2 U1401.3(FB_B1)
N30048929: RJ1400.2 U1400.2(FB_B0)
N30048931: RJ1401.2 U1400.3(FB_B1)
N30067324: C707.1 D1.1(CATHODE) F1.1 Q5.1(S1) Q5.2(S2) Q5.3(S3) U8.4(ANODE)
N30067326: D1.2(ANODE) D2.2(ANODE)
N30067898: C706.2 U8.7(VCAPH)
N30067927: Q5.4(G) U8.2(GT_PULL_DWN) U8.6(GATE_DRV)
N30067937: C706.1 U8.1(VCAPL)
N30116863: DS5.2(ANODE) R9387.2
N30116879: DS5.1(cathode) Q2033.D
N30193355: R1417.1 U1401.10(CLKIN/GPO2)
N30341641: U8045.1(B) U8046.5(Q)
N30341647: R9495.2 SW8002.3(B) SW8002.4(BB) U8044.3(~{MR})
N30341735: R9494.2 U8044.1(~{RESE}T) U8046.7(PRE)
N30341753: R9496.1 R9505.2 U8046.1(CLK)
N30345760: C8253.1 U8047.6(CT)
N30957696: C303.1 R461.2
N30957697: C307.1 R464.2
N45361223: Q3.4(G) R457.1
N45364158: Q4.4(G) R456.1
N46501256: C318.1 U92.6(CT)

Not connected (* = marked no-connect by the designer): EXP_P4 23 24 25 26; J6000 4(ID)*; U8 3(NC3)* 5(NC5)*; U23 2(NC.2) 3(NC.3) 18(NC.18) 36(NC.36) 37(EXTSUP); U1008 3(ALERT/NC.3); U1017 3(ALERT/NC.3); U1018 3(ALERT/NC.3); U1020 3(ALERT/NC.3); U1022 3(ALERT/NC.3); U1023 3(ALERT/NC.3); U1024 3(ALERT/NC.3); U1025 3(ALERT/NC.3); U1026 3(ALERT/NC.3); U2000 22(PPS) 40(WOL_INT) 42(SON) 43(SO) 45(SI) 46(SIP); U6000 5(NC); U6002 2(NC)*; U6003 21(ADBUS4/DTR#/GPIOL0) 22(ADBUS5/DSR#/GPIOL1) 23(ADBUS6/DCD#/GPIOL2) 24(ADBUS7/RI#/GPIOL3) 30(BCBUS4/DTR#/GPIOL0) 32(BCBUS5/DSR#/GPIOL1) 33(BCBUS6/BCD#/GPIOL2) 34(BCBUS7/RI#/GPIOL3) 36(SUSPEND#) 43(CDBUS4/DTR#) 44(CDBUS5/DSR#) 45(CDBUS6/DCD#) 46(CDBUS7/RI#) 55(DDBUS4/DTR#) 57(DDBUS5/DSR#) 58(DDBUS6/DCD#) 59(DDBUS7/RI#); U8044 4(CT)*; U8046 3(QN)*

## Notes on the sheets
sheet 10
- Note:  FTDI Power sourced from USB.
- Silkscreen: FTDI_VBUS
- Note:  Buffers used for voltage translation
  and signal isolation.
- Terminal Port A
  / UART1
- Terminal
  Connector
- RTS#
- TXD
- RXD
- CTS#
- Silkscreen: TERMINAL
- Terminal Port B
  / UART2
- Note:  FTDI EEPROM for storing manufacturing/configuration information.
- Digikey no: XC1118CT-ND
  Manufactor no: ECS-120-20-30B-TR
- Terminal Port C
  / UART3
sheet 11
- For 1.8V remove
  0-ohm, swap the
  .1uf and 1uf caps
- SELECTS 1.2V CORE
- 2.5V
- VDDH_REG IS 2.5V MAX.  MDIO CAN
  TOLLERATE 3.3V INPUTS.
- [ETH0_RSTn]
- [ETH0_EXP_RSTn]
- RESET FOR EACH PHY SO THAT IF TWO PHYS ARE
  AT THE SAME ADDRESS ONE CAN BE DISABLED BY
  ASSERTING IT'S RESET.  ALSO HELPS WITH MFG
  TEST TO HOLD THE NON-TARGETED PHY IN RESET.
- [ETH1_EXP_RSTn]
sheet 12
- NOT AUTO TEMP
- 10 Volts
- 10TPB100ML
- Less than ESR 35m-ohm
- Fsw = 400KHZ
- 10 Volts
- Less than ESR 35m-ohm
- GRM32ER61A476KE20L (1210-10V)
  T525D476M016ATE035 (7343-16V)
- 100uF total
- ~5.07V
- BIAS THE ENABLES, AND
  DEBOUNCE THE PUSH BUTTON.
  PB_ON_DG DRIVES BSS138 FET
  WITH ~2.5V THRESHOLD.
- VBATT
  12v
- Input
- PMON INSERTED HERE
- OPTIONAL FAN CONNECTOR
- ER40
sheet 13
- ER21
- => <"EVM/SVB Power Rails/Nets">
- PCB Notes:
  Non-current carrying nets
  Route as psuedo-Diff Pair
  using min trace width
  no impedance requirement.
- => VDD_DSPEVE_AVS
- => VDD_CORE_AVS
- => VDDA_DPLL_1V8
  => VDDA_ANA_1V8
- => Not Used
- OTP ID = 0x2A
- PCB Notes:
  Non-current carrying nets
  Route as psuedo-Diff Pair
  using min trace width
  no impedance requirement.
- => VDDS_1V8
  => VDDS_DDR_1V8
  => VDDS_PoP_1V8
  => VDD_SHV_1V8
  => VPRH_1V8
- => VDD_DDR_DV
- => Not Used
- => Not Used
- OTP ID = 0x2E
- Reset
  Circuit
- PMIC POWER GOOD INDICATOR
- Note: Power-On Reset To CPU
- Silkscreen: BUTTON_PORZ
- Note: Warm Reset to CPU
- Silkscreen: BUTTON_RESET
- Note: CPU Reset From Emulator
sheet 14
- PULLUP TIED TO
  VPRH_1V8 TO PREVENT
  MOMENTARY TURN ON
  DURING POWER UP.
  TPS22965 ENABLE IS
  1.2V.
- REV E
- ER51
- VIH (ON) 1.2V min
- ER23
sheet 15
- 100-0000
- 100-0110
- 100-0001
- 100-0111
- 100-1000
- 100-0010
- 100-1001
- 100-0011
- 100-1010
